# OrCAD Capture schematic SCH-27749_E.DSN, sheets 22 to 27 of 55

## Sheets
22 T4240 Grounds: size C
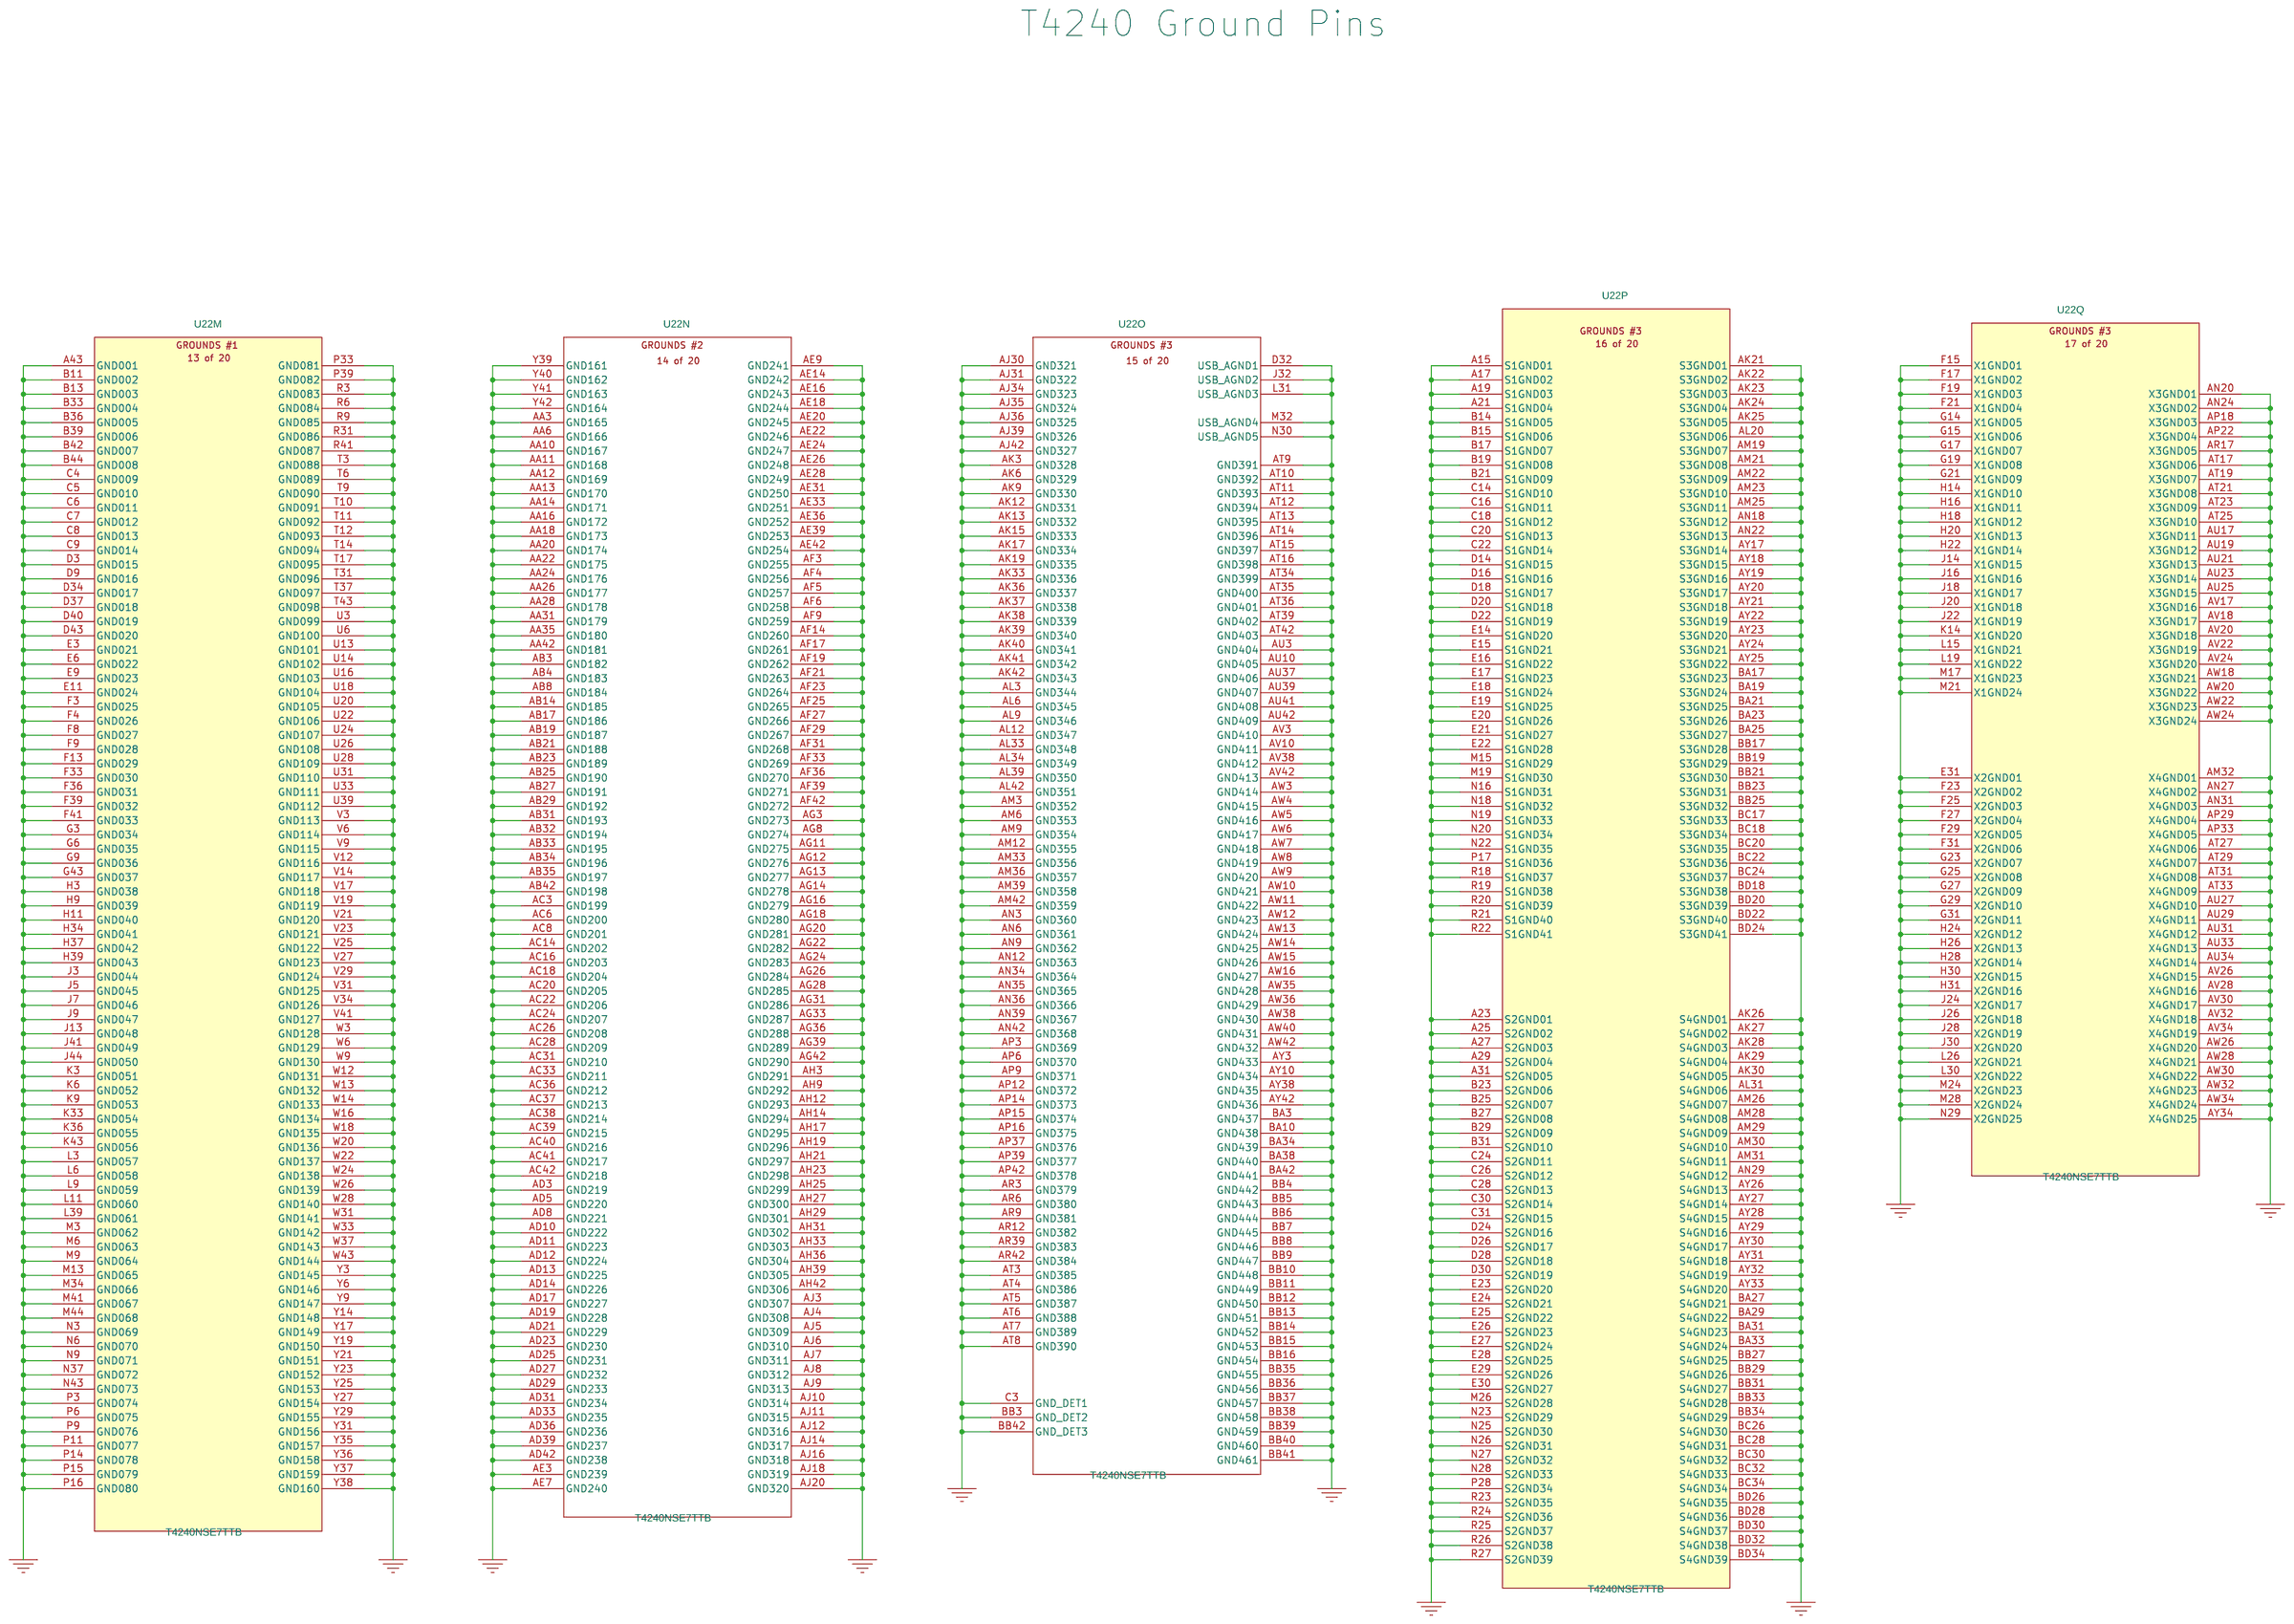
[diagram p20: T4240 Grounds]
23 T4240 NC: size C
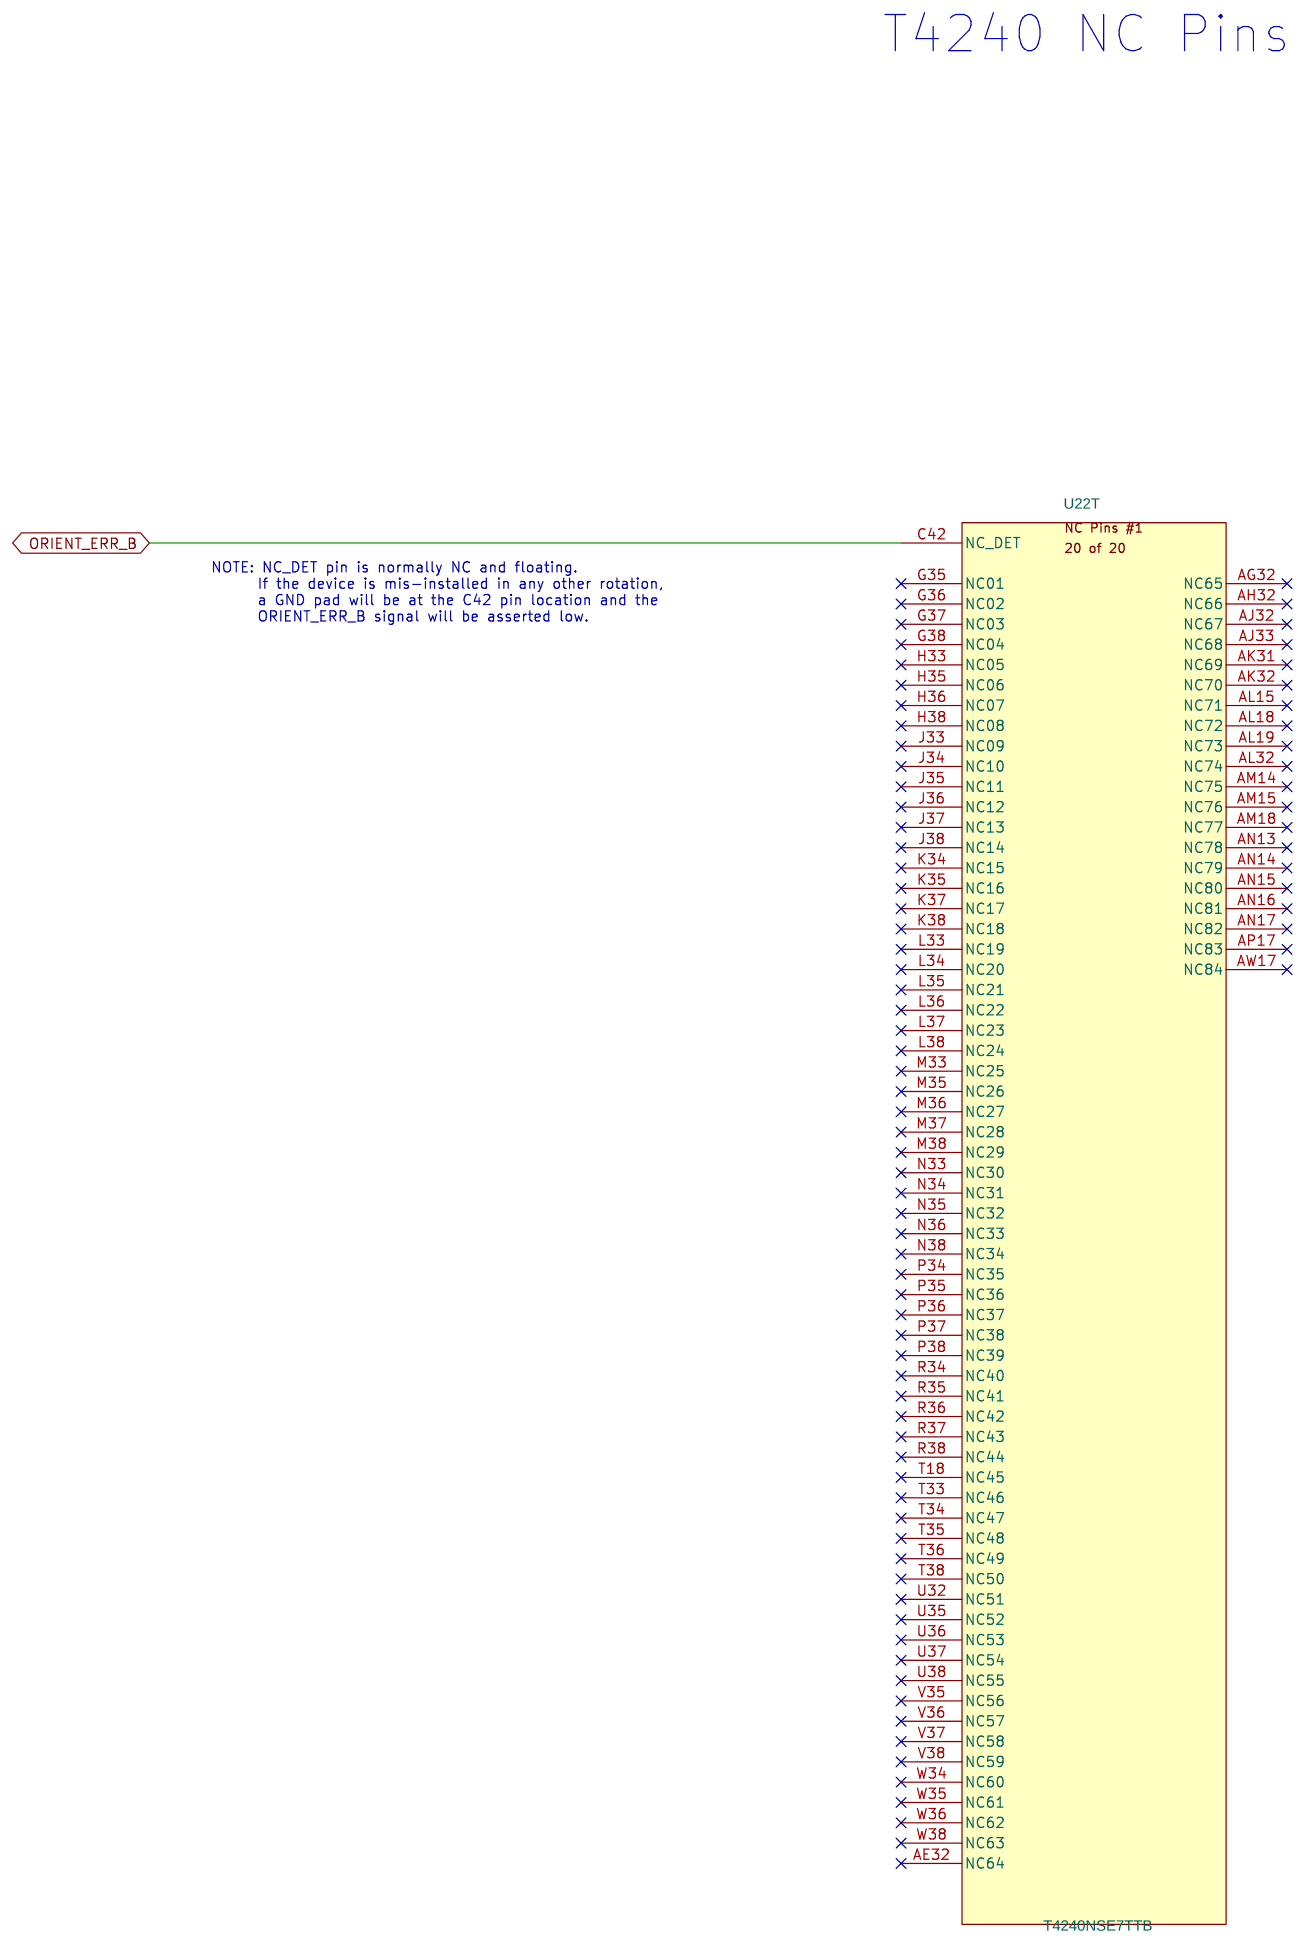
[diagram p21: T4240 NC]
24 Clock Generator: size C
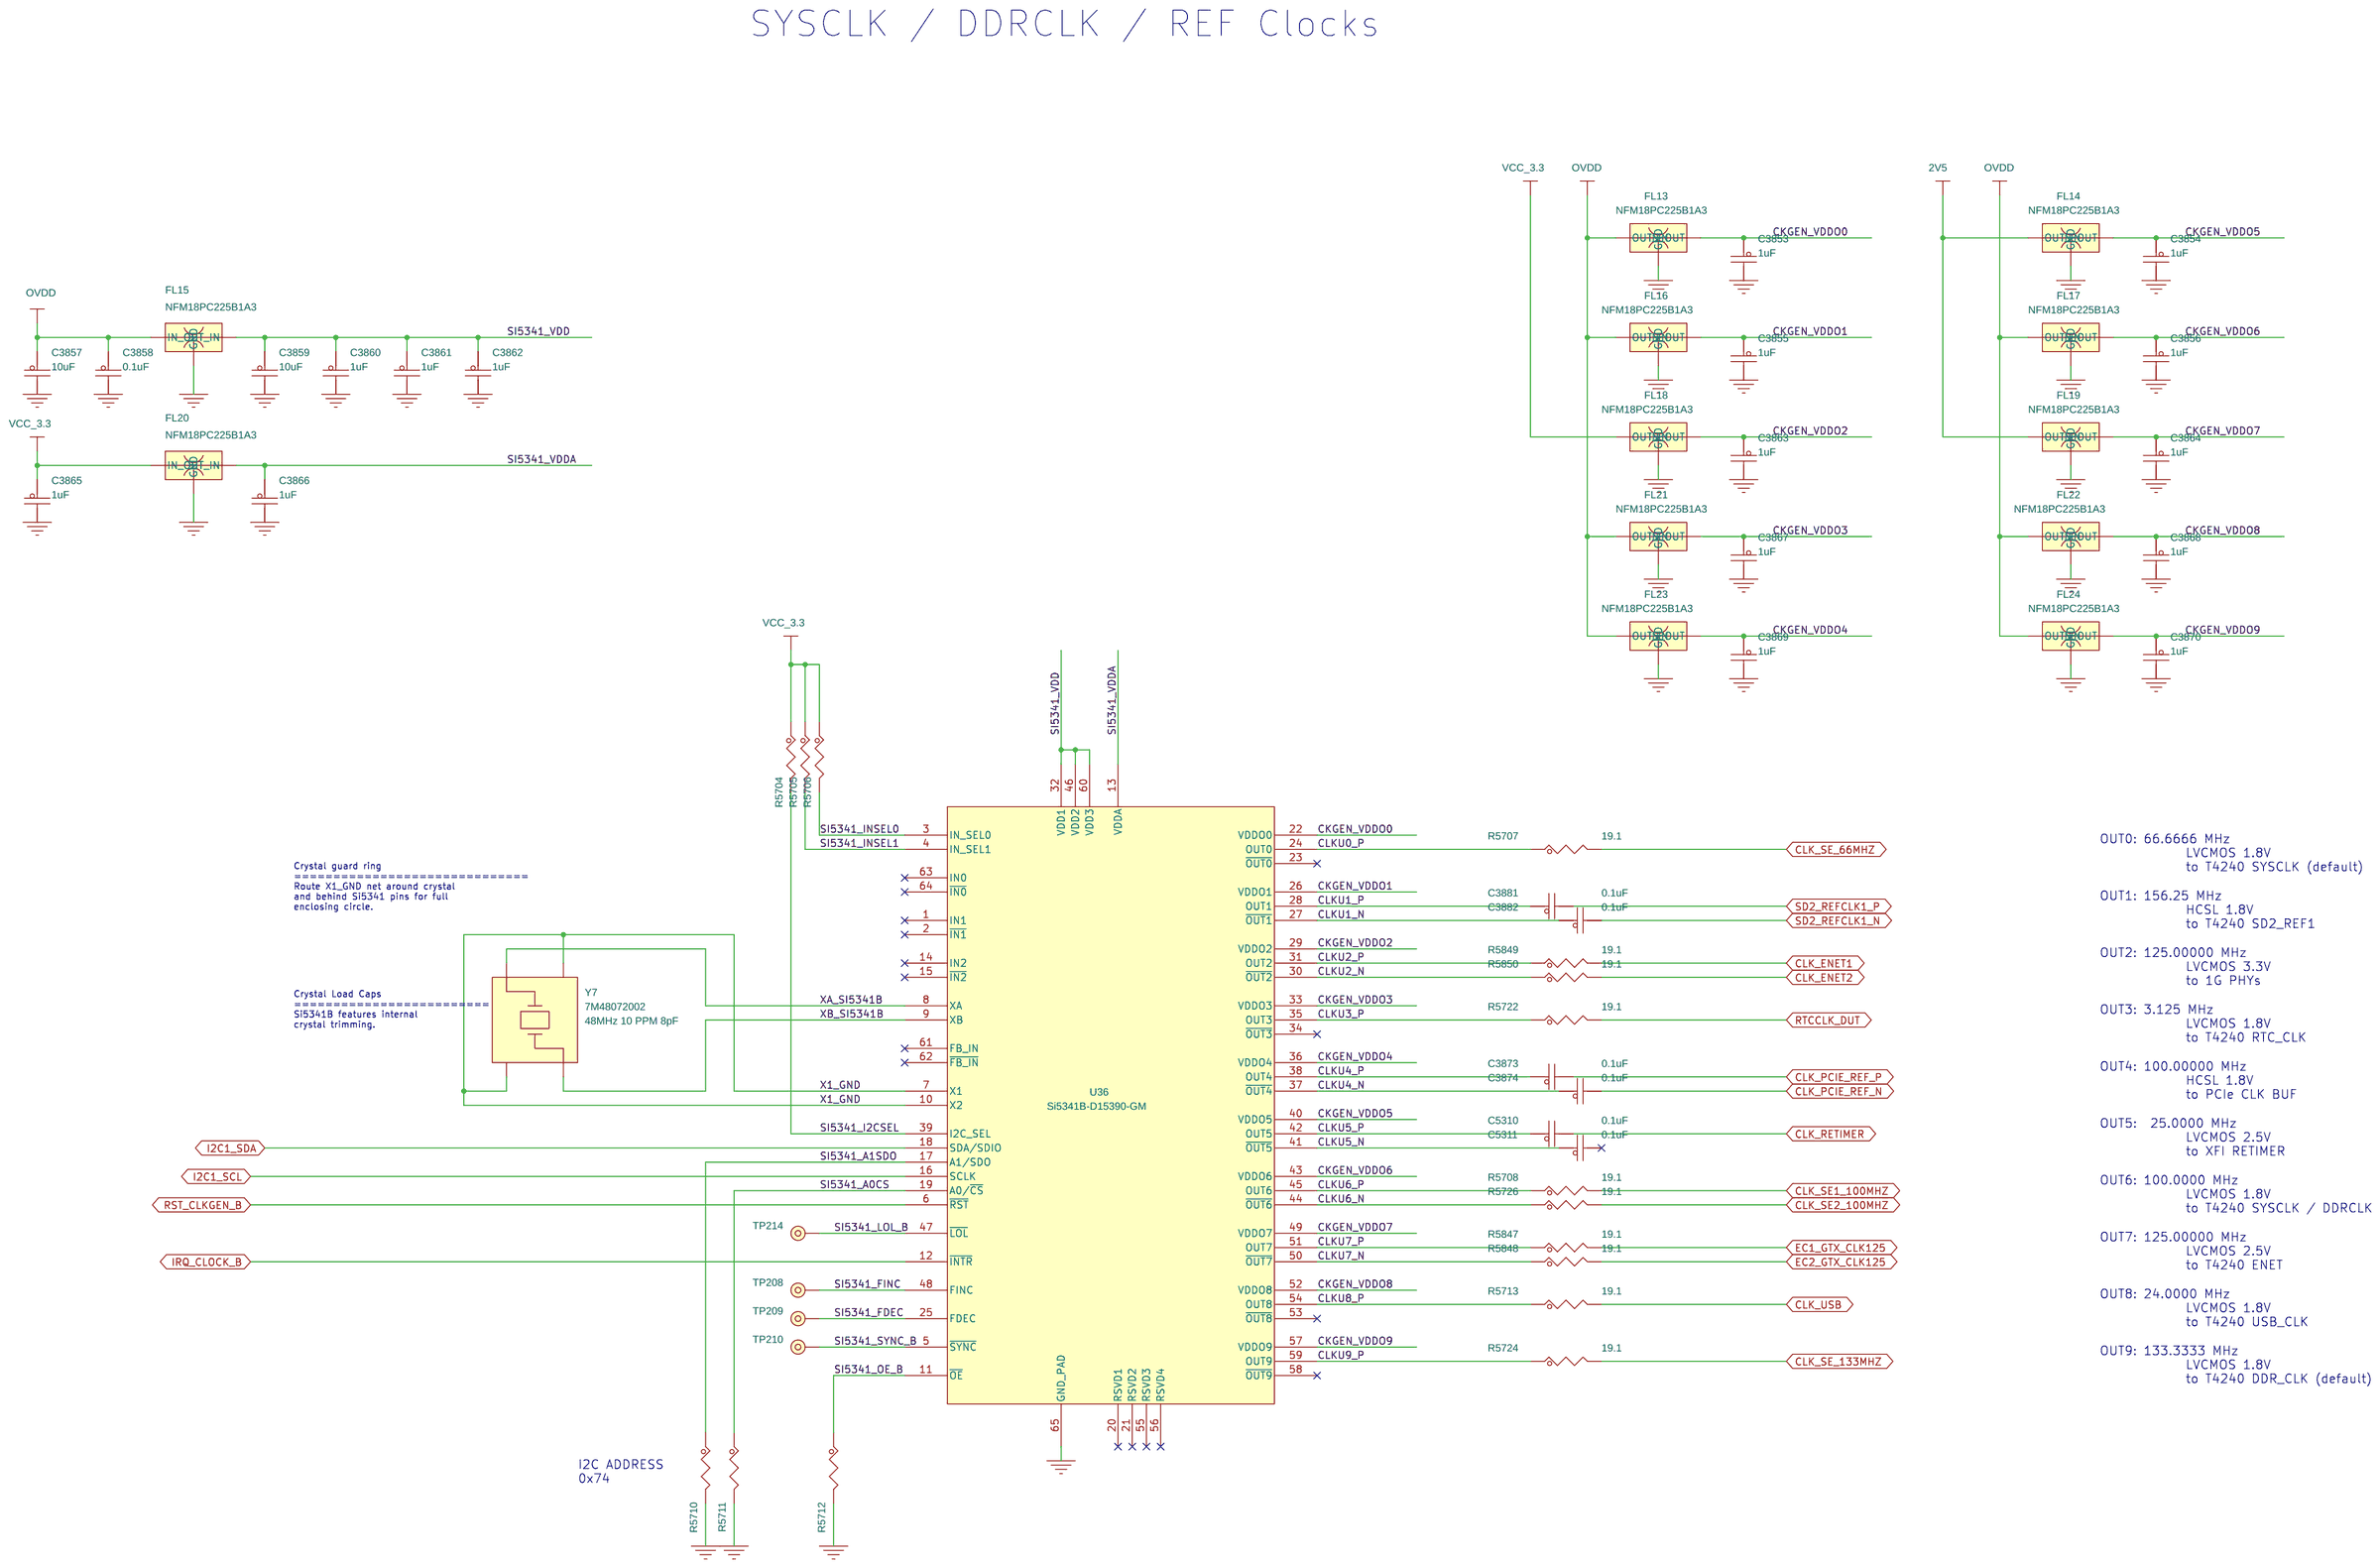
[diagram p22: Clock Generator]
25 PCIe & DUT Clock Buffers: size C
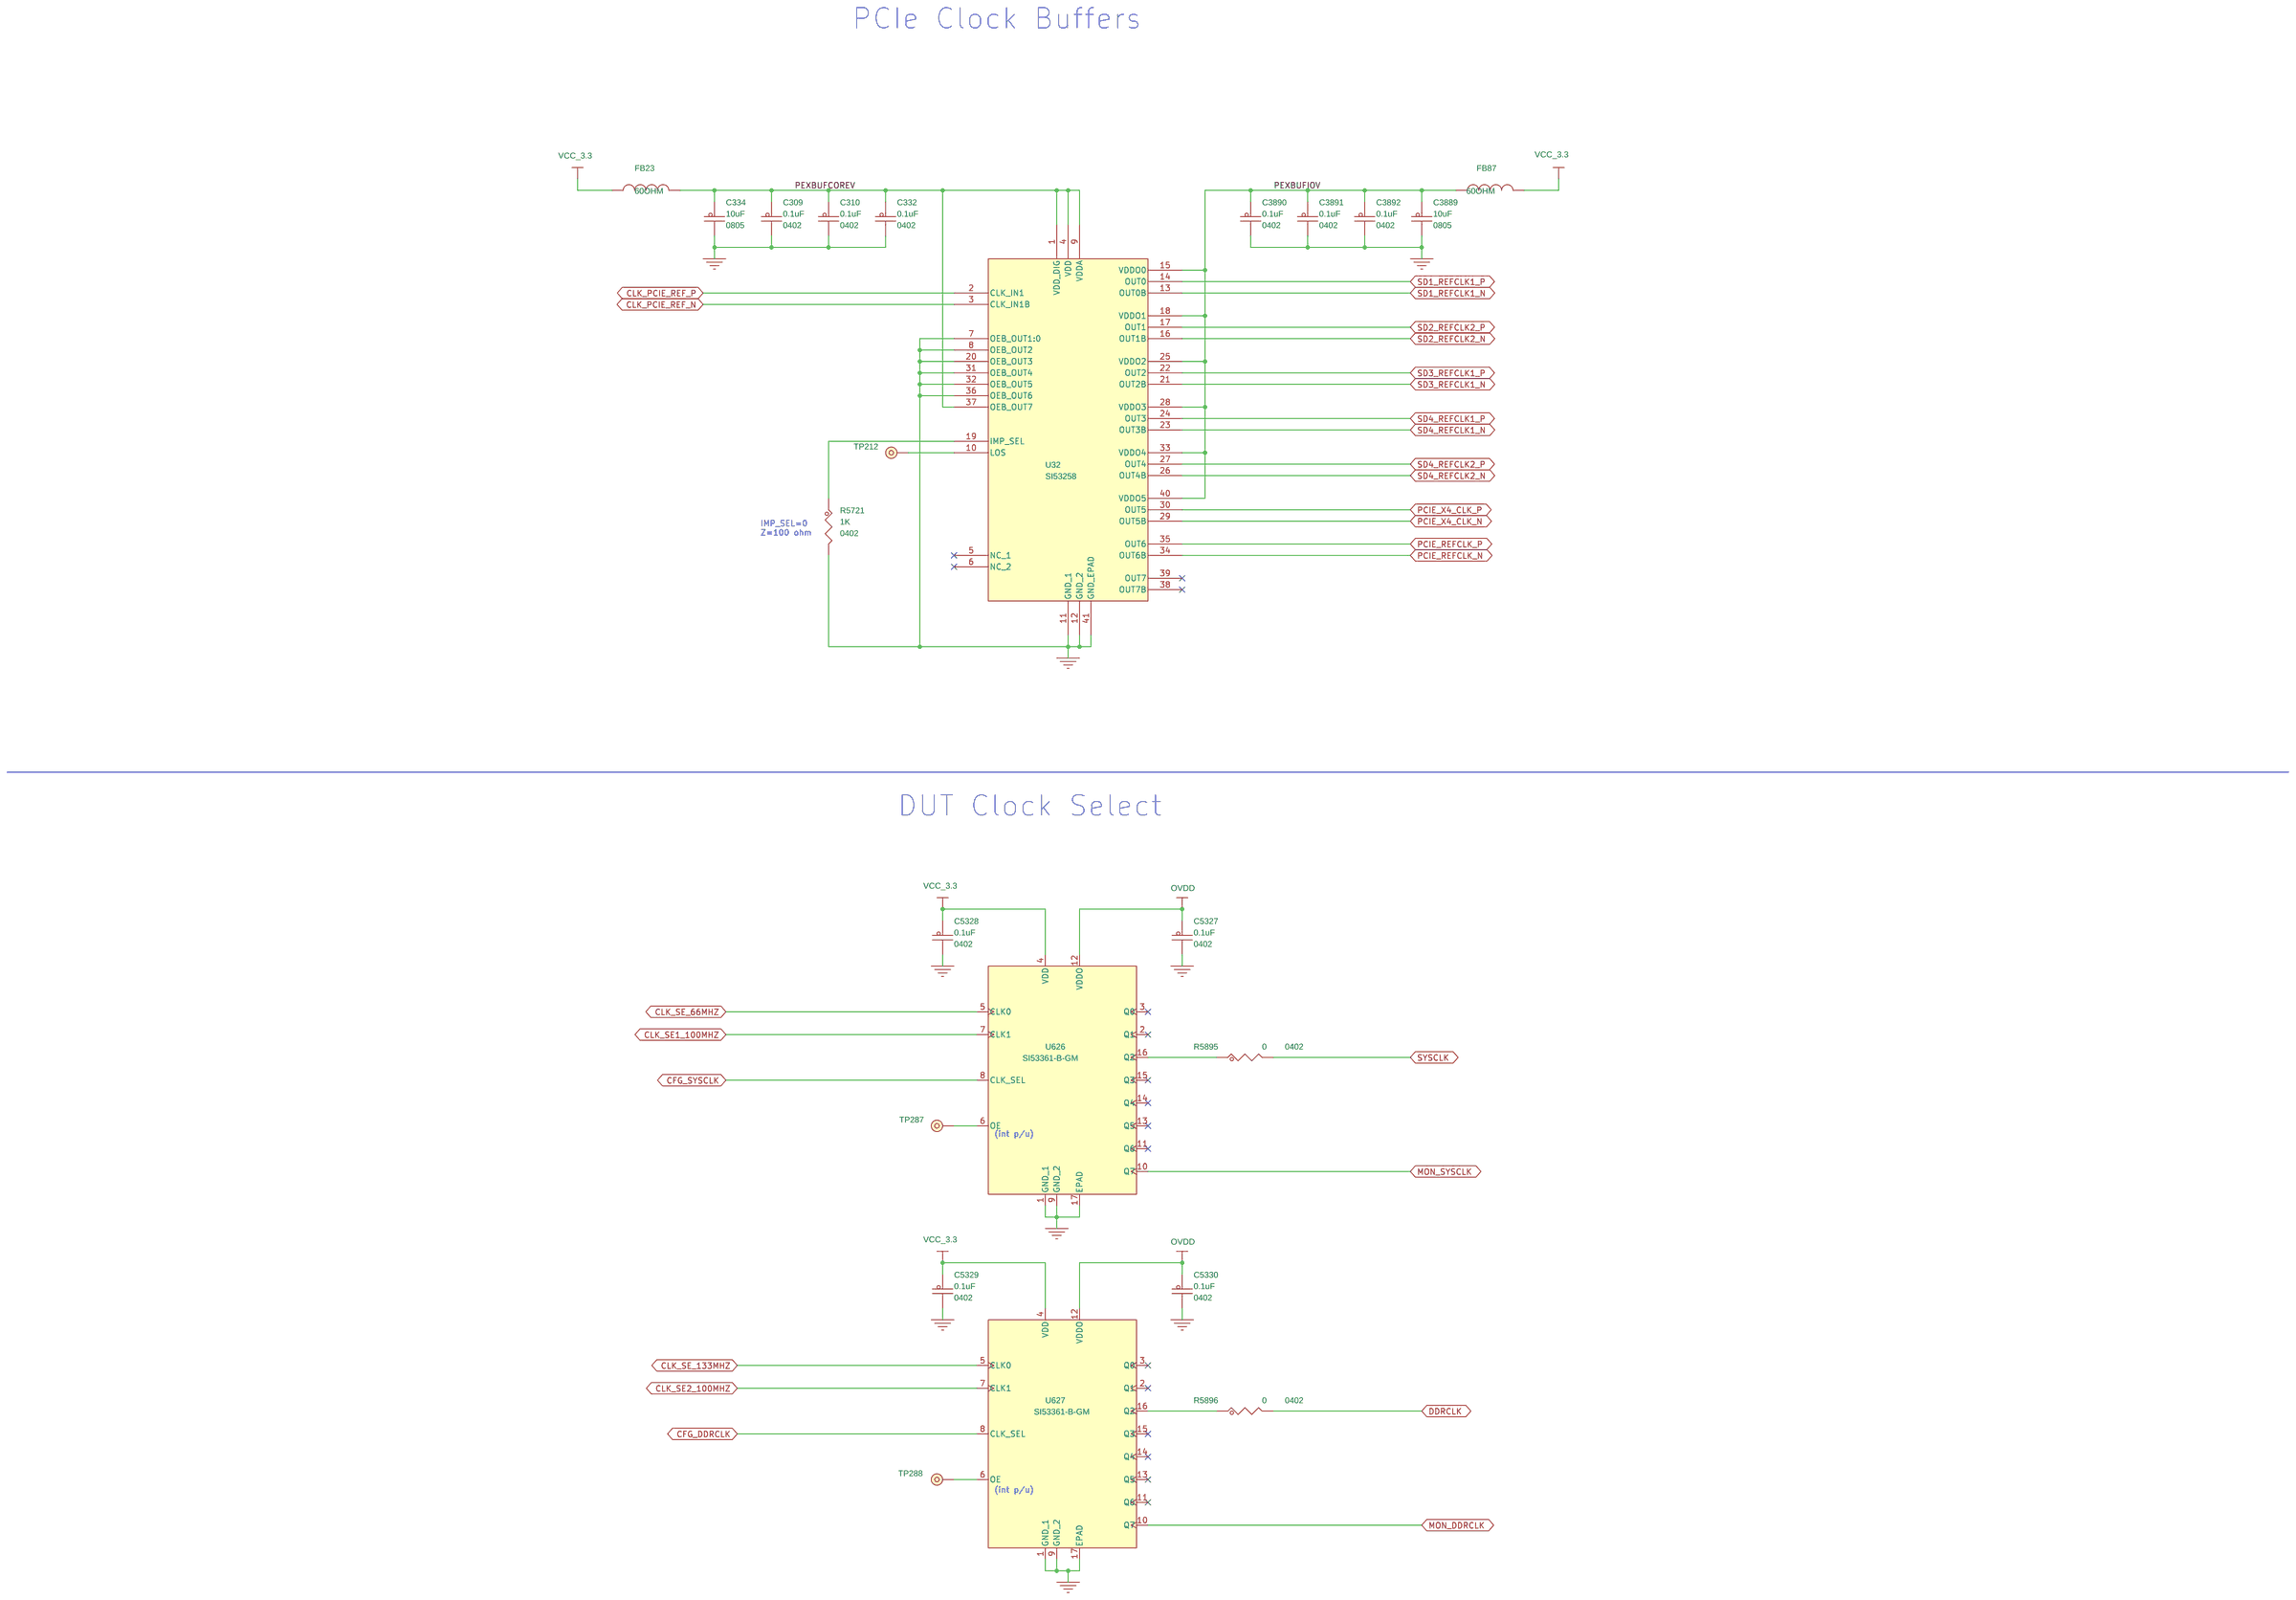
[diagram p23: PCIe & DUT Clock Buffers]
26 reserved (2)
27 T4240 System Block + COP: size C
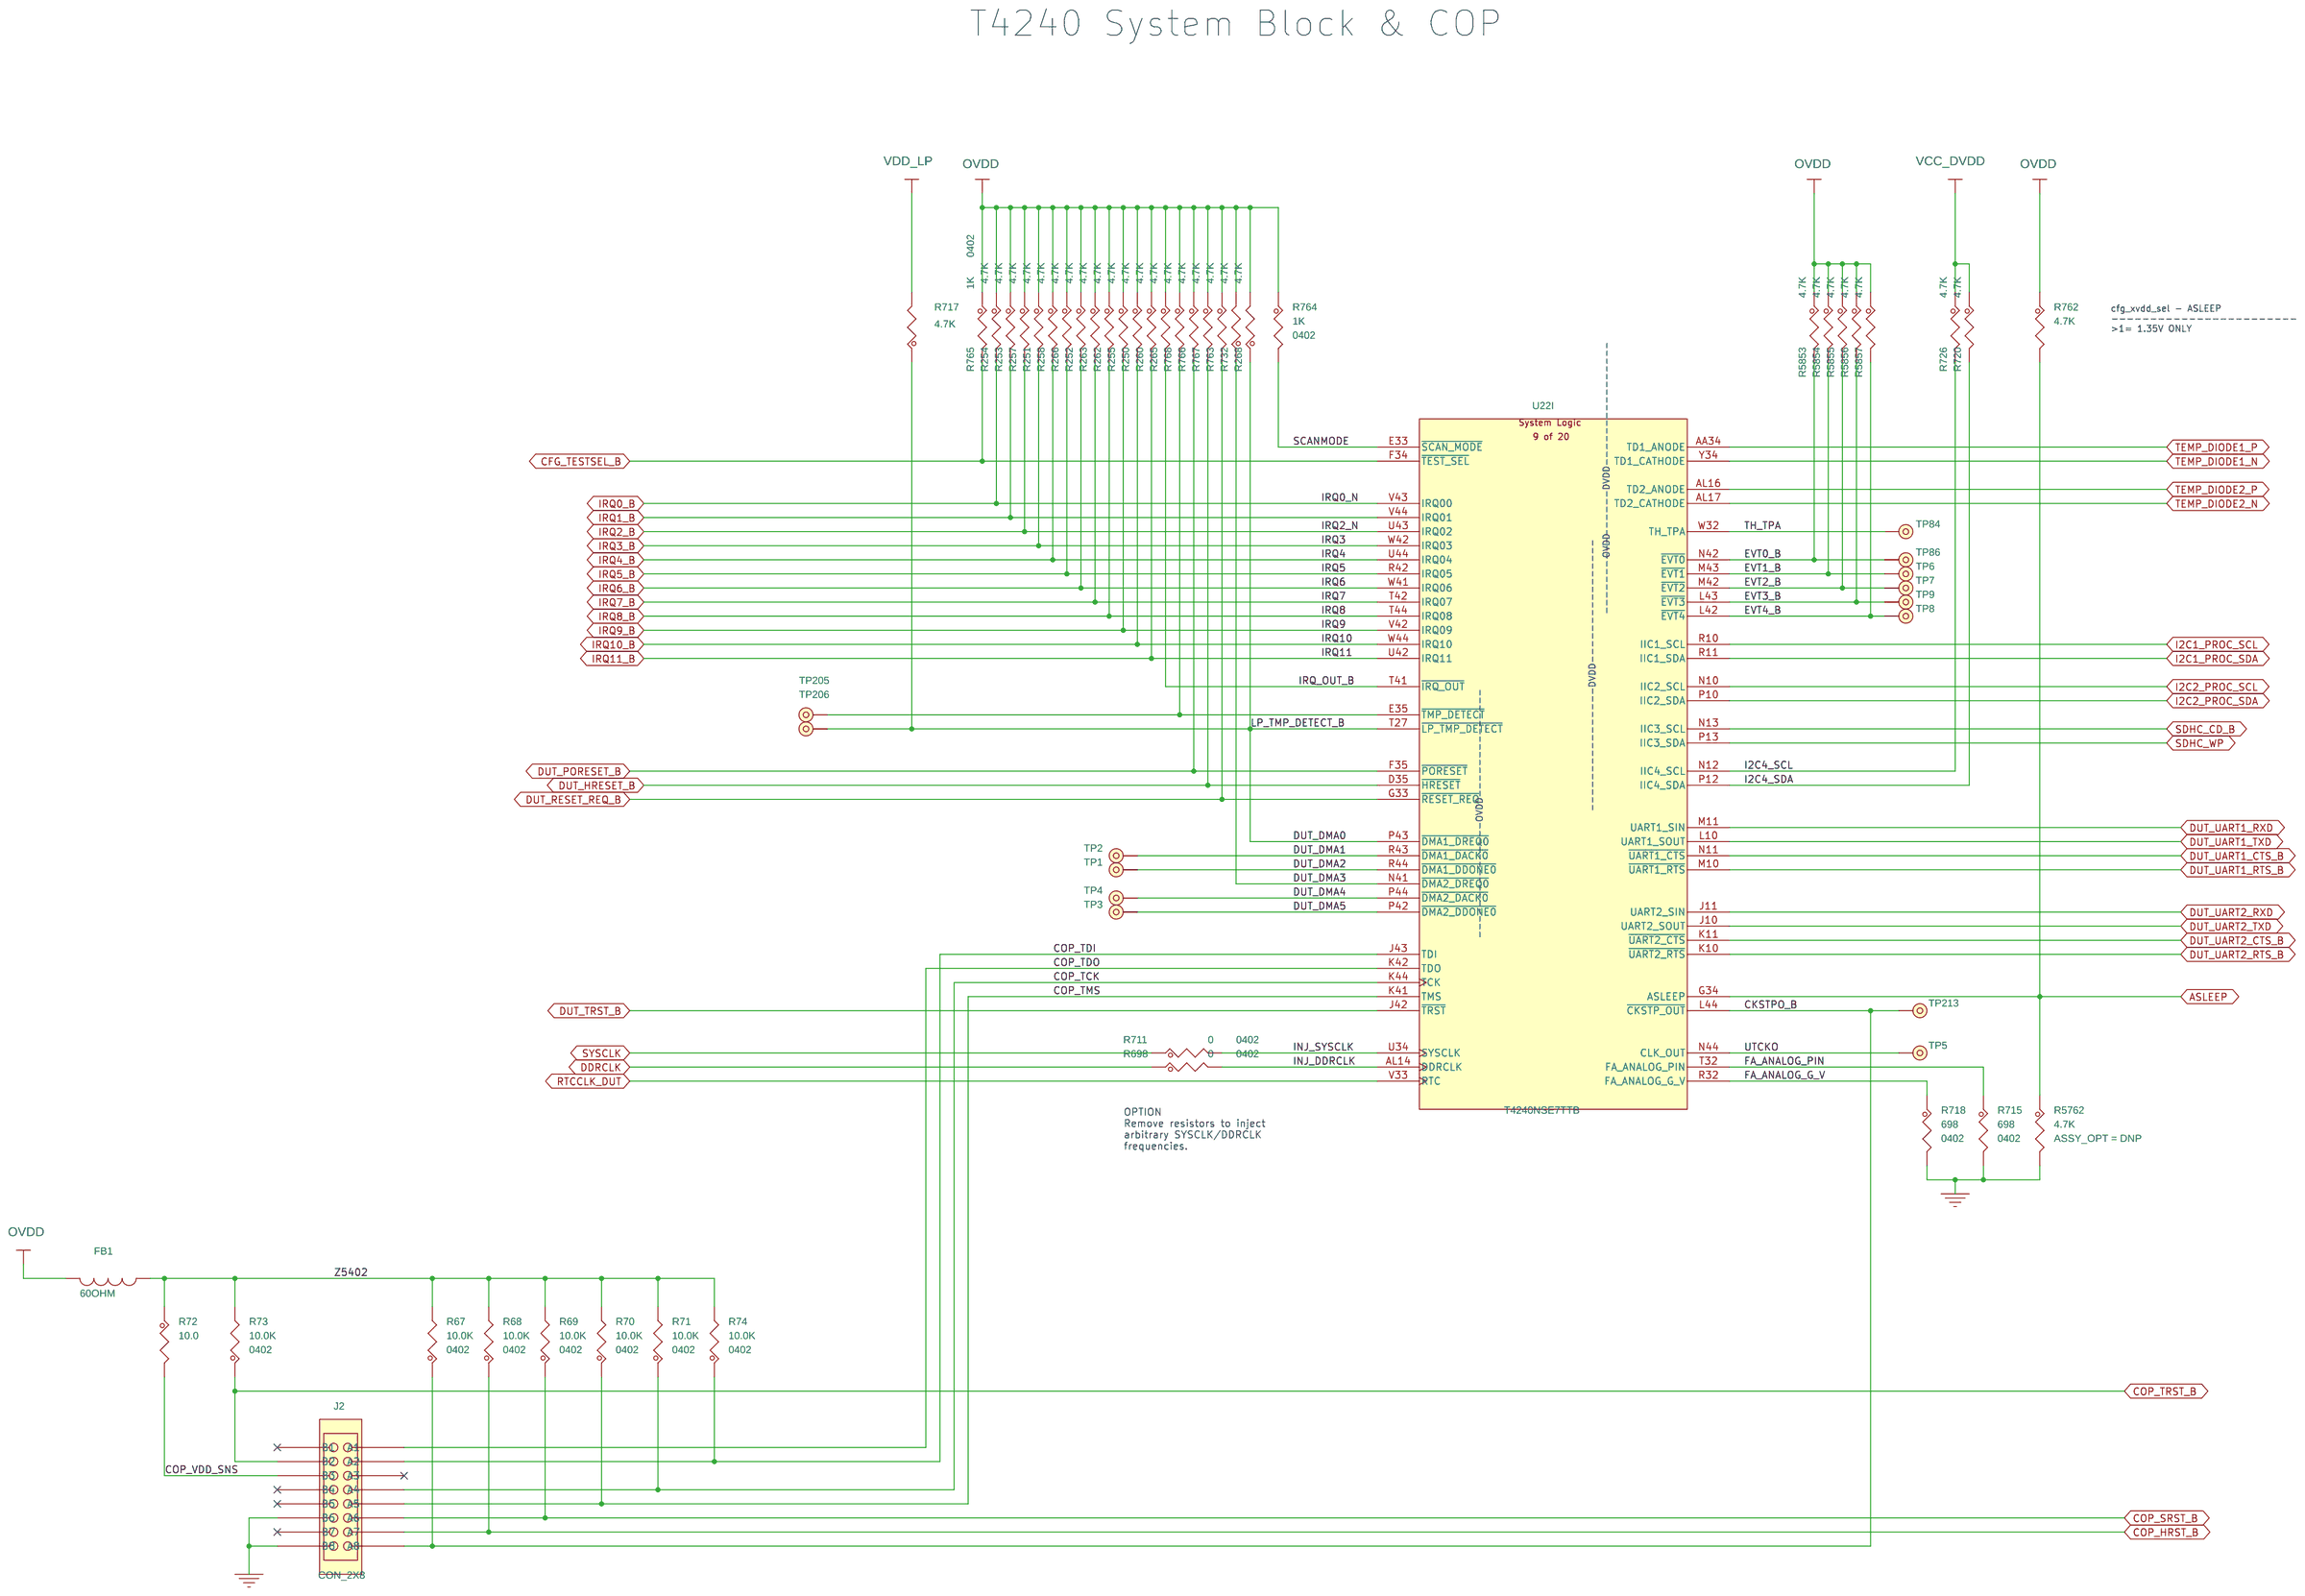
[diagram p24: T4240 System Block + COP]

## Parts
sheet Clock Generator
C3853  1uF  [CC0402_HD]
C3854  1uF  [CC0402_HD]
C3855  1uF  [CC0402_HD]
C3856  1uF  [CC0402_HD]
C3857  10uF  [CC0603_OV]
C3858  0.1uF  [CC0402_HD]
C3859  10uF  [CC0603_OV]
C3860  1uF  [CC0402_HD]
C3861  1uF  [CC0402_HD]
C3862  1uF  [CC0402_HD]
C3863  1uF  [CC0402_HD]
C3864  1uF  [CC0402_HD]
C3865  1uF  [CC0402_HD]
C3866  1uF  [CC0402_HD]
C3867  1uF  [CC0402_HD]
C3868  1uF  [CC0402_HD]
C3869  1uF  [CC0402_HD]
C3870  1uF  [CC0402_HD]
C3873  0.1uF  [CC0402_HD]
C3874  0.1uF  [CC0402_HD]
C3881  0.1uF  [CC0402_HD]
C3882  0.1uF  [CC0402_HD]
C5310  0.1uF  [CC0402_HD]
C5311  0.1uF  [CC0402_HD]
FL13  NFM18PC225B1A3  [cc0603_nfm18pc]
FL14  NFM18PC225B1A3  [cc0603_nfm18pc]
FL15  NFM18PC225B1A3  [cc0603_nfm18pc]
FL16  NFM18PC225B1A3  [cc0603_nfm18pc]
FL17  NFM18PC225B1A3  [cc0603_nfm18pc]
FL18  NFM18PC225B1A3  [cc0603_nfm18pc]
FL19  NFM18PC225B1A3  [cc0603_nfm18pc]
FL20  NFM18PC225B1A3  [cc0603_nfm18pc]
FL21  NFM18PC225B1A3  [cc0603_nfm18pc]
FL22  NFM18PC225B1A3  [cc0603_nfm18pc]
FL23  NFM18PC225B1A3  [cc0603_nfm18pc]
FL24  NFM18PC225B1A3  [cc0603_nfm18pc]
R5704  4.7K  [RC0402_25]
R5705  4.7K  [RC0402_25]
R5706  4.7K  [RC0402_25]
R5707  19.1  [RC0402_25]
R5708  19.1  [RC0402_25]
R5710  4.7K  [RC0402_25]
R5711  4.7K  [RC0402_25]
R5712  4.7K  [RC0402_25]
R5713  19.1  [RC0402_25]
R5722  19.1  [RC0402_25]
R5724  19.1  [RC0402_25]
R5726  19.1  [RC0402_25]
R5847  19.1  [RC0402_25]
R5848  19.1  [RC0402_25]
R5849  19.1  [RC0402_25]
R5850  19.1  [RC0402_25]
TP208  TPAD_020  [tpad_020_top]
TP209  TPAD_020  [tpad_020_top]
TP210  TPAD_020  [tpad_020_top]
TP214  TPAD_020  [tpad_020_top]
U36  Si5341B-D15390-GM  [qfn64_0p5_9x9c]
Y7  7M48072002  [xtal_4_3p3x2p6mm]
sheet PCIe & DUT Clock Buffers
C309  0.1uF  [CC0402_HD]
C310  0.1uF  [CC0402_HD]
C332  0.1uF  [CC0402_HD]
C334  10uF  [CC0603_OV]
C3889  10uF  [CC0603_OV]
C3890  0.1uF  [CC0402_HD]
C3891  0.1uF  [CC0402_HD]
C3892  0.1uF  [CC0402_HD]
C5327  0.1uF  [CC0402_HD]
C5328  0.1uF  [CC0402_HD]
C5329  0.1uF  [CC0402_HD]
C5330  0.1uF  [CC0402_HD]
FB23  60OHM  [ind_1p8x1mm_sm]
FB87  60OHM  [ind_1p8x1mm_sm]
R5721  1K  [RC0402_25]
R5895  0  [RC0402_25]
R5896  0  [RC0402_25]
TP212  TPAD_020  [tpad_020_top]
TP287  TPAD_020  [tpad_020_top]
TP288  TPAD_020  [tpad_020_top]
U32  SI53258  [qfn40_0p5_6x6_4p6ep]
U626  SI53361-B-GM  [qfn16_0p5_3x3mm]
U627  SI53361-B-GM  [qfn16_0p5_3x3mm]
sheet T4240 DDR Controller #2
U22  T4240NSE7TTB  [BGA1932_1MM_45X45MM]  (sections A,B,C,D,E,F,G,H,I,J,K,L,M,N,O,P,Q,R,S,T)
sheet T4240 System Block + COP
FB1  60OHM  [ind_1p8x1mm_sm]
J2  CON_2X8  [HDR208_4W]
R67  10.0K  [RC0402_25]
R68  10.0K  [RC0402_25]
R69  10.0K  [RC0402_25]
R70  10.0K  [RC0402_25]
R71  10.0K  [RC0402_25]
R72  10.0  [RC0402_25]
R73  10.0K  [RC0402_25]
R74  10.0K  [RC0402_25]
R250  4.7K  [RC0402_25]
R251  4.7K  [RC0402_25]
R252  4.7K  [RC0402_25]
R253  4.7K  [RC0402_25]
R254  4.7K  [RC0402_25]
R255  4.7K  [RC0402_25]
R257  4.7K  [RC0402_25]
R258  4.7K  [RC0402_25]
R260  4.7K  [RC0402_25]
R262  4.7K  [RC0402_25]
R263  4.7K  [RC0402_25]
R265  4.7K  [RC0402_25]
R266  4.7K  [RC0402_25]
R268  4.7K  [RC0402_25]
R698  0  [RC0402_25]
R711  0  [RC0402_25]
R715  698  [RC0402_25]
R717  4.7K  [RC0402_25]
R718  698  [RC0402_25]
R720  4.7K  [RC0402_25]
R726  4.7K  [RC0402_25]
R732  4.7K  [RC0402_25]
R762  4.7K  [RC0402_25]
R763  4.7K  [RC0402_25]
R764  1K  [RC0402_25]
R765  1K  [RC0402_25]
R766  4.7K  [RC0402_25]
R767  4.7K  [RC0402_25]
R768  4.7K  [RC0402_25]
R5762  4.7K  [RC0402_25]
R5853  4.7K  [RC0402_25]
R5854  4.7K  [RC0402_25]
R5855  4.7K  [RC0402_25]
R5856  4.7K  [RC0402_25]
R5857  4.7K  [RC0402_25]
TP1  TPAD_020  [tpad_020_top]
TP2  TPAD_020  [tpad_020_top]
TP3  TPAD_020  [tpad_020_top]
TP4  TPAD_020  [tpad_020_top]
TP5  TPAD_020  [tpad_020_top]
TP6  TPAD_020  [tpad_020_top]
TP7  TPAD_020  [tpad_020_top]
TP8  TPAD_020  [tpad_020_top]
TP9  TPAD_020  [tpad_020_top]
TP84  TPAD_020  [tpad_020_top]
TP86  TPAD_020  [tpad_020_top]
TP205  TPAD_020  [tpad_020_top]
TP206  TPAD_020  [tpad_020_top]
TP213  TPAD_020  [tpad_020_top]

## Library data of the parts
C3853-C3856 C3860-C3870 = CAP_NP: CAP CER 1uF 10V 10% X7S 0402; AGILE_PN: 150-80357; CAD_APPROVED: Yes; FPLIST: CC0402_25,CC0402_HD,0402_CC,capc0402_l; HEIGHT: 0.6MM; MFG_NAME01: MURATA; MFG_PN01: GRM155C71A105KE11D; Package Size: 0402; ROHS: Yes; Rated Voltage: 10V; SIGNAL_MODEL: DEFAULT_CAPACITOR_1e+06pF_2_1; Temp Range: -55C to +125C; Tolerance: 10%; VOLTAGE: 10V
C3857 C3859 = CAP_NP: CAP CER 10UF 10V 10% X5R 0603; AGILE_PN: 150-78675; CAD_APPROVED: Yes; FPLIST: CC0603_OV,CC0603,0603_CC; HEIGHT: 1.016MM; MFG_NAME01: MURATA; MFG_PN01: GRM188R61A106KE69D; PRIORITY_PN: 021-00358; ROHS: Yes; ROOM: SDHC; Rated Voltage: 10V; SIGNAL_MODEL: DEFAULT_CAPACITOR_1e+07pF_2_1; TOL: 10%; Temp Range: -55C to +85C; Temp_Range: -55°C ~ 85°C; Tolerance: 10%; VOLTAGE: 10v
C3858 = CAP_NP: CAP CER 0.1uF 16V 10% X7R AEC-Q200 0402; AGILE_PN: 150-79025; CAD_APPROVED: Yes; FPLIST: CC0402_25,CC0402_HD,0402_CC,capc0402_l; HEIGHT: 0.55MM; MFG_NAME01: MURATA; MFG_PN01: GCM155R71C104KA55D; PRIORITY_PN: 021-00389; Package Size: 0402; Package Type: ø180mm Reel PAPER; ROHS: Yes; ROOM: RS232; Rated Voltage: 16V; SIGNAL_MODEL: DEFAULT_CAPACITOR_100000pF_2_1; TOL: 10%; Temp Range: -55C to +125C; Tolerance: 10%; VOLTAGE: 35V
C3873 C3874 C3881 C3882 C5310 C5311 = CAP_NP: CAP CER 0.1uF 16V 10% X7R AEC-Q200 0402; AGILE_PN: 150-79025; CAD_APPROVED: Yes; FPLIST: CC0402_25,CC0402_HD,0402_CC,capc0402_l; HEIGHT: 0.55MM; MFG_NAME01: MURATA; MFG_PN01: GCM155R71C104KA55D; PRIORITY_PN: 021-00389; Package Size: 0402; Package Type: ø180mm Reel PAPER; ROHS: Yes; ROOM: MII_MUX; Rated Voltage: 16V; Temp Range: -55C to +125C; Tolerance: 10%; VOLTAGE: 35V
FL13-FL24 = NFM18PC225B1A3: CAP FILTER EMI 2.2uF 10V 20% -- 0603; 3D_Mechanical_Footprint_File: http://fcl.am.freescale.net/ALLEGRO/step/cc0603_nfm18pc.STEP; AGILE_PN: 150-79428; CAD_APPROVED: Yes; HEIGHT: 0.9MM; MFG_NAME01: MURATA; MFG_PN01: NFM18PC225B1A3D; ROHS: Yes; Rated Voltage: 10V; Temp Range: -40C to +85C; Temp_Range: -40 C to +85 C; Tolerance: 20%; VOLTAGE: 10V
R5704-R5706 R5710-R5712 = RES: RES MF 4.7K 1/10W 5% AEC-Q200 0402; AGILE_PN: 470-82064; CAD_APPROVED: Yes; FPLIST: RC0402_25,RC0402_HD,0402_CC,RC0402_X2; HEIGHT: 0.41mm; MFG_NAME01: KOA SPEER; MFG_PN01: RK73B1ETTP472J; PRIORITY_PN: 006-00619; ROHS: Yes; ROOM: DUT_CLOSE; SIGNAL_MODEL: DEFAULT_RESISTOR_4700OHM_2_1; TOL: 1%; Temp Range: -55C to +155C; Tolerance: 5%; VOLTAGE: 1/16W
R5707 R5708 R5713 R5722 R5724 R5726 R5847-R5850 = RES: RES MF 19.1 OHM 1/10W 1% AEC-Q200 0402; AGILE_PN: 470-30669; CAD_APPROVED: Yes; FPLIST: RC0402_25,RC0402_HD,0402_CC; HEIGHT: 0.40 MM; MFG_NAME01: KOA SPEER; MFG_PN01: RK73H1ETTP19R1F; ROHS: Yes; Temp Range: -55°C to +155°C; Temp_Range: -55°C to +155°C; Tolerance: 1%; VOLTAGE: 50V
TP1-TP9 TP84 TP86 TP205 TP206 TP208-TP210 TP212-TP214 TP287 TP288 = T_POINT_TH: TEST POINT PAD 20 MILS SMT, NOT PART TO ORDER; AGILE_PN: 211-81036; CAD_APPROVED: Yes; FPLIST: tpad_020_top,tpad_020_btm_nsp; HEIGHT: 0.127MM; MFG_NAME01: NO PART ORDER; MFG_PN01: NA; ROHS: Yes
U36 = Si5341B_64P_EP: IC CLK MUX 4:10 DIFF LVPECL/LVDS 350MHz 1.8V/3.3V QFN64; 3D_Mechanical_Footprint_File: http://fcl.am.freescale.net/ALLEGRO/step/qfn64_0p5_9x9c.step; AGILE_PN: 312-83853; CAD_APPROVED: Yes; HEIGHT: 0.90 MM; MFG_NAME01: SKYWORKS SOLUTIONS, INC.; ROHS: Yes; Temp Range: -40C to +85C; VOLTAGE: 1.8V/3.3V
Y7 = XTAL_13Y: XTAL 48MHz 10PPM 8pF SMD; AGILE_PN: 230-78080; CAD_APPROVED: Yes; HEIGHT: 0.8MM; MFG_NAME01: TXC CORP; NOTE: 48MHz 10 PPM 8pF; ROHS: Yes
C309 C310 C332 C3890-C3892 C5327-C5330 = CAP_NP: CAP CER 0.1uF 16V 10% X7R AEC-Q200 0402; AGILE_PN: 150-79025; CAD_APPROVED: Yes; FPLIST: CC0402_25,CC0402_HD,0402_CC,capc0402_l; HEIGHT: 0.55MM; MFG_NAME01: MURATA; MFG_PN01: GCM155R71C104KA55D; Package: 0402; Package Size: 0402; Package Type: ø180mm Reel PAPER; Part Number: 4CC104B163X00; Product Name: (H)MLCC 0.1uF/16V +-10% 0402 X7R; ROHS: Yes; Rated Voltage: 16V; Temp Range: -55C to +125C; Tolerance: 10%
C334 C3889 = CAP_NP: CAP CER 10UF 10V 10% X5R 0603; AGILE_PN: 150-78675; CAD_APPROVED: Yes; FPLIST: CC0603_OV,CC0603,0603_CC_NSP; HEIGHT: 1.016MM; MFG_NAME01: MURATA; MFG_PN01: GRM188R61A106KE69D; Package: 0805; Part Number: 4CC106D101X00; Product Name: (H)MLCC 10uF/10V +/-10% 0805 X5R; ROHS: Yes; Rated Voltage: 10V; Temp Range: -55C to +85C; Tolerance: 10%
FB1 FB23 FB87 = INDUCTOR: IND FER BEAD 60OHM@100MHz 3A 25% 0603; 3D_Mechanical_Footprint_File: http://fcl.am.freescale.net/ALLEGRO/step/ind_1p8x1mm_sm.step; AGILE_PN: 180-78461; CAD_APPROVED: Yes; HEIGHT: 1MM; MFG_NAME01: WURTH ELEKTRONIK EISOS GMBH & CO. KG (ELECTRONIC & ELECTROMEHANICAL COMP); MFG_PN01: 742792602; ROHS: Yes
R764 R765 R5721 = RES: RES 1K 1/16W 5% 0402; AGILE_PN: 470-80721; CAD_APPROVED: Yes; FPLIST: RC0402_25,RC0402_HD,0402_CC; HEIGHT: 0.4 MM; MFG_NAME01: TE CONNECTIVITY LTD; MFG_PN01: CRG0402J1K0; Package: 0402; Part Number: 4RC1002B11X00; Product Name: (H)RES 1K 1/16W 0402 1% PBFREE; ROHS: Yes; Tolerance: 5%
R698 R711 R5895 R5896 = RES: RES MF ZERO OHM 1/10W -- 0402; AGILE_PN: 470-79965; CAD_APPROVED: Yes; FPLIST: RC0402_25,RC0402_HD,RC0402_X2,0402_CC,RC0402_X3; HEIGHT: 0.4MM; MFG_NAME01: PANASONIC; MFG_PN01: ERJ-2GE0R00X; Package: 0402; Part Number: 4RC0000B51X00; Product Name: (H)RES 0E 1/16W 0402 5% PBFREE; ROHS: Yes; Temp Range: –55 °C to +155 °C
U32 = Si53258: IC CLK BUFF 8 CLK-OUT PCIE 100MHz 1.8-3.3V QFN40; AGILE_PN: 312-82930; CAD_APPROVED: Yes; HEIGHT: 0.9MM; MFG_NAME01: SILICON LABORATORIES; MFG_PN01: SI53258A-D01AM; ROHS: Yes; Temp Range: -40C to +105C; VOLTAGE: 1.8-3.3V
U626 U627 = SI53361: IC CLK BUF LOW JITTER 2:1 INPUT MUX 200MHz 1.71-3.63V QFN16; 3D_Mechanical_Footprint_File: http://fcl.am.freescale.net/ALLEGRO/step/qfn16_0p5_3x3mm.STEP; AGILE_PN: 312-83879; CAD_APPROVED: yes; HEIGHT: 0.9 MM; MFG_NAME01: Skyworks Solutions Inc.; Package Size: 16-QFN Exposed Pad; ROHS: Yes; Supply Voltage: 1.71V ~ 3.63V; Temp Range: -40  °C  +85 °C
U22 = T4240: IC MPU 64BIT T4240 1.8GHz 1.025V CRYPTO QorIQ PBGA1932; 3D_Mechanical_Footprint_File: http://fcl.am.freescale.net/ALLEGRO/step/bga1932_1mm_45x45mm.STEP; AGILE_PN: 330-77243; CAD_APPROVED: Yes; HEIGHT: 3.33 MM; MFG_NAME01: NXP SEMICONDUCTOR; Package Size: SOT1645-1; Part Number: 71F101G206X01; Product Name: (N)SOC FREESCALE:T4240NSE7TTB; ROHS: Yes; Temp Range: 0 to 105 °C
J2 = CONN_SHRHDR_8X2: CON 2X8 PLUG SHRD TH 100MIL CTR 365H AU 130L; 3D_Mechanical_Footprint_File: http://fcl.am.freescale.net/ALLEGRO/step/hdr208_4w.STEP; AGILE_PN: 210-75459; CAD_APPROVED: Yes; HEIGHT: 9.27 MM; MFG_NAME01: SAMTEC; MFG_PN01: TST-108-01-S-D; Package Size: TH-16; Package Type: TH; ROHS: Yes
R67-R71 R73 R74 = RES: RES MF 10.0K 1/16W 1% AEC-Q200 0402; AGILE_PN: 470-75416; CAD_APPROVED: Yes; FPLIST: RC0402_25,RC0402_HD,0402_CC; HEIGHT: 0.4MM; MFG_NAME01: KOA SPEER; MFG_PN01: RK73H1ETTP1002F; Package: 0402; Part Number: 4RC1003B11X00; Product Name: (H)RES 10K 1/16W 0402 1% PBFREE; ROHS: Yes; Temp Range: –55 °C to +155 °C; Tolerance: 1%
R72 = RES: RES MF 10.0 OHM 1/16W 1% 0402; 3D_Mechanical_Footprint_File: http://fcl.am.freescale.net/ALLEGRO/step/rc0402_25.STEP; AGILE_PN: 470-76090; CAD_APPROVED: Yes; FPLIST: RC0402_25,RC0402_HD,0402_CC,rc0402_ghwe; HEIGHT: 0.4MM; MFG_NAME01: BOURNS; MFG_PN01: CR0402-FX-10R0GLF; Part Number: 4RC1000C11X00; Product Name: (H)RES 10E 1/10W 0603 1% PBFREE; ROHS: Yes; Tolerance: 1%
R250-R255 R257 R258 R260 R262 R263 R265 R266 R268 R717 R720 R726 R732 R762 R763 R766-R768 R5853-R5857 = RES: RES MF 4.7K 1/10W 5% AEC-Q200 0402; AGILE_PN: 470-82064; CAD_APPROVED: Yes; FPLIST: RC0402_25,RC0402_HD,0402_CC,RC0402_X2; HEIGHT: 0.41mm; MFG_NAME01: KOA SPEER; MFG_PN01: RK73B1ETTP472J; ROHS: Yes; Temp Range: -55C to +155C; Tolerance: 5%
R715 R718 = RES: RES MF 698 OHM 1/16W 1% ACE-Q200 0402; AGILE_PN: 470-78342; CAD_APPROVED: Yes; FPLIST: RC0402_25,RC0402_HD,0402_CC; HEIGHT: 0.4MM; MFG_NAME01: KOA SPEER; MFG_PN01: RK73H1ETTP6980F; Package: 0402; Part Number: 4RC6981B11X00; Product Name: (H)RES 698E 1/16W 0402 1% PBFREE; ROHS: Yes; Tolerance: 1%
R5762 = RES: RES MF 4.7K 1/10W 5% AEC-Q200 0402; AGILE_PN: 470-82064; ASSY_OPT: DNP; CAD_APPROVED: Yes; FPLIST: RC0402_25,RC0402_HD,0402_CC,RC0402_X2; HEIGHT: 0.41mm; MFG_NAME01: KOA SPEER; MFG_PN01: RK73B1ETTP472J; ROHS: Yes; Temp Range: -55C to +155C; Tolerance: 5%

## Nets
2V5: FL14.3(OUT_IN) FL19.3(OUT_IN) ; also on sheet 15 20 38 45
GND: C309.2 C310.2 C332.2 C334.2 C3853.2 C3854.2 C3855.2 C3856.2 C3857.2 C3858.2 C3859.2 C3860.2 C3861.2 C3862.2 C3863.2 C3864.2 C3865.2 C3866.2 C3867.2 C3868.2 C3869.2 C3870.2 C3889.2 C3890.2 C3891.2 C3892.2 C5327.2 C5328.2 C5329.2 C5330.2 FL13.2(GND) FL14.2(GND) FL15.2(GND) FL16.2(GND) FL17.2(GND) FL18.2(GND) FL19.2(GND) FL20.2(GND) FL21.2(GND) FL22.2(GND) FL23.2(GND) FL24.2(GND) J2.12(B6) J2.16(B8) R715.2 R718.2 R5710.2 R5711.2 R5712.2 R5721.2 R5762.2 U22.A15(S1GND01) U22.A17(S1GND02) U22.A19(S1GND03) U22.A21(S1GND04) U22.A23(S2GND01) U22.A25(S2GND02) U22.A27(S2GND03) U22.A29(S2GND04) U22.A31(S2GND05) U22.A43(GND001) U22.AA3(GND165) U22.AA6(GND166) U22.AA10(GND167) U22.AA11(GND168) U22.AA12(GND169) U22.AA13(GND170) U22.AA14(GND171) U22.AA16(GND172) U22.AA18(GND173) U22.AA20(GND174) U22.AA22(GND175) U22.AA24(GND176) U22.AA26(GND177) U22.AA28(GND178) U22.AA31(GND179) U22.AA35(GND180) U22.AA42(GND181) U22.AB3(GND182) U22.AB4(GND183) U22.AB8(GND184) U22.AB14(GND185) U22.AB17(GND186) U22.AB19(GND187) U22.AB21(GND188) U22.AB23(GND189) U22.AB25(GND190) U22.AB27(GND191) U22.AB29(GND192) U22.AB31(GND193) U22.AB32(GND194) U22.AB33(GND195) U22.AB34(GND196) U22.AB35(GND197) U22.AB42(GND198) U22.AC3(GND199) U22.AC6(GND200) U22.AC8(GND201) U22.AC14(GND202) U22.AC16(GND203) U22.AC18(GND204) U22.AC20(GND205) U22.AC22(GND206) U22.AC24(GND207) U22.AC26(GND208) U22.AC28(GND209) U22.AC31(GND210) U22.AC33(GND211) U22.AC36(GND212) U22.AC37(GND213) U22.AC38(GND214) U22.AC39(GND215) U22.AC40(GND216) U22.AC41(GND217) U22.AC42(GND218) U22.AD3(GND219) U22.AD5(GND220) U22.AD8(GND221) U22.AD10(GND222) U22.AD11(GND223) U22.AD12(GND224) U22.AD13(GND225) U22.AD14(GND226) U22.AD17(GND227) U22.AD19(GND228) U22.AD21(GND229) U22.AD23(GND230) U22.AD25(GND231) U22.AD27(GND232) U22.AD29(GND233) U22.AD31(GND234) U22.AD33(GND235) U22.AD36(GND236) U22.AD39(GND237) U22.AD42(GND238) U22.AE3(GND239) U22.AE7(GND240) U22.AE9(GND241) U22.AE14(GND242) U22.AE16(GND243) U22.AE18(GND244) U22.AE20(GND245) U22.AE22(GND246) U22.AE24(GND247) U22.AE26(GND248) U22.AE28(GND249) U22.AE31(GND250) U22.AE33(GND251) U22.AE36(GND252) U22.AE39(GND253) U22.AE42(GND254) U22.AF3(GND255) U22.AF4(GND256) U22.AF5(GND257) U22.AF6(GND258) U22.AF9(GND259) U22.AF14(GND260) U22.AF17(GND261) U22.AF19(GND262) U22.AF21(GND263) U22.AF23(GND264) U22.AF25(GND265) U22.AF27(GND266) U22.AF29(GND267) U22.AF31(GND268) U22.AF33(GND269) U22.AF36(GND270) U22.AF39(GND271) U22.AF42(GND272) U22.AG3(GND273) U22.AG8(GND274) U22.AG11(GND275) U22.AG12(GND276) U22.AG13(GND277) U22.AG14(GND278) U22.AG16(GND279) U22.AG18(GND280) U22.AG20(GND281) U22.AG22(GND282) U22.AG24(GND283) U22.AG26(GND284) U22.AG28(GND285) U22.AG31(GND286) U22.AG33(GND287) U22.AG36(GND288) U22.AG39(GND289) U22.AG42(GND290) U22.AH3(GND291) U22.AH9(GND292) U22.AH12(GND293) U22.AH14(GND294) U22.AH17(GND295) U22.AH19(GND296) U22.AH21(GND297) U22.AH23(GND298) U22.AH25(GND299) U22.AH27(GND300) U22.AH29(GND301) U22.AH31(GND302) U22.AH33(GND303) U22.AH36(GND304) U22.AH39(GND305) U22.AH42(GND306) U22.AJ3(GND307) U22.AJ4(GND308) U22.AJ5(GND309) U22.AJ6(GND310) U22.AJ7(GND311) U22.AJ8(GND312) U22.AJ9(GND313) U22.AJ10(GND314) U22.AJ11(GND315) U22.AJ12(GND316) U22.AJ14(GND317) U22.AJ16(GND318) U22.AJ18(GND319) U22.AJ20(GND320) U22.AJ30(GND321) U22.AJ31(GND322) U22.AJ34(GND323) U22.AJ35(GND324) U22.AJ36(GND325) U22.AJ39(GND326) U22.AJ42(GND327) U22.AK3(GND328) U22.AK6(GND329) U22.AK9(GND330) U22.AK12(GND331) U22.AK13(GND332) U22.AK15(GND333) U22.AK17(GND334) U22.AK19(GND335) U22.AK21(S3GND01) U22.AK22(S3GND02) U22.AK23(S3GND03) U22.AK24(S3GND04) U22.AK25(S3GND05) U22.AK26(S4GND01) U22.AK27(S4GND02) U22.AK28(S4GND03) U22.AK29(S4GND04) U22.AK30(S4GND05) U22.AK33(GND336) U22.AK36(GND337) U22.AK37(GND338) U22.AK38(GND339) U22.AK39(GND340) U22.AK40(GND341) U22.AK41(GND342) U22.AK42(GND343) U22.AL3(GND344) U22.AL6(GND345) U22.AL9(GND346) U22.AL12(GND347) U22.AL20(S3GND06) U22.AL31(S4GND06) U22.AL33(GND348) U22.AL34(GND349) U22.AL39(GND350) U22.AL42(GND351) U22.AM3(GND352) U22.AM6(GND353) U22.AM9(GND354) U22.AM12(GND355) U22.AM19(S3GND07) U22.AM21(S3GND08) U22.AM22(S3GND09) U22.AM23(S3GND10) U22.AM25(S3GND11) U22.AM26(S4GND07) U22.AM28(S4GND08) U22.AM29(S4GND09) U22.AM30(S4GND10) U22.AM31(S4GND11) U22.AM32(X4GND01) U22.AM33(GND356) U22.AM36(GND357) U22.AM39(GND358) U22.AM42(GND359) U22.AN3(GND360) U22.AN6(GND361) U22.AN9(GND362) U22.AN12(GND363) U22.AN18(S3GND12) U22.AN20(X3GND01) U22.AN22(S3GND13) U22.AN24(X3GND02) U22.AN27(X4GND02) U22.AN29(S4GND12) U22.AN31(X4GND03) U22.AN34(GND364) U22.AN35(GND365) U22.AN36(GND366) U22.AN39(GND367) U22.AN42(GND368) U22.AP3(GND369) U22.AP6(GND370) U22.AP9(GND371) U22.AP12(GND372) U22.AP14(GND373) U22.AP15(GND374) U22.AP16(GND375) U22.AP18(X3GND03) U22.AP22(X3GND04) U22.AP29(X4GND04) U22.AP33(X4GND05) U22.AP37(GND376) U22.AP39(GND377) U22.AP42(GND378) U22.AR3(GND379) U22.AR6(GND380) U22.AR9(GND381) U22.AR12(GND382) U22.AR17(X3GND05) U22.AR39(GND383) U22.AR42(GND384) U22.AT3(GND385) U22.AT4(GND386) U22.AT5(GND387) U22.AT6(GND388) U22.AT7(GND389) U22.AT8(GND390) U22.AT9(GND391) U22.AT10(GND392) U22.AT11(GND393) U22.AT12(GND394) U22.AT13(GND395) U22.AT14(GND396) U22.AT15(GND397) U22.AT16(GND398) U22.AT17(X3GND06) U22.AT19(X3GND07) U22.AT21(X3GND08) U22.AT23(X3GND09) U22.AT25(X3GND10) U22.AT27(X4GND06) U22.AT29(X4GND07) U22.AT31(X4GND08) U22.AT33(X4GND09) U22.AT34(GND399) U22.AT35(GND400) U22.AT36(GND401) U22.AT39(GND402) U22.AT42(GND403) U22.AU3(GND404) U22.AU10(GND405) U22.AU17(X3GND11) U22.AU19(X3GND12) U22.AU21(X3GND13) U22.AU23(X3GND14) U22.AU25(X3GND15) U22.AU27(X4GND10) U22.AU29(X4GND11) U22.AU31(X4GND12) U22.AU33(X4GND13) U22.AU34(X4GND14) U22.AU37(GND406) U22.AU39(GND407) U22.AU41(GND408) U22.AU42(GND409) U22.AV3(GND410) U22.AV10(GND411) U22.AV17(X3GND16) U22.AV18(X3GND17) U22.AV20(X3GND18) U22.AV22(X3GND19) U22.AV24(X3GND20) U22.AV26(X4GND15) U22.AV28(X4GND16) U22.AV30(X4GND17) U22.AV32(X4GND18) U22.AV34(X4GND19) U22.AV38(GND412) U22.AV42(GND413) U22.AW3(GND414) U22.AW4(GND415) U22.AW5(GND416) U22.AW6(GND417) U22.AW7(GND418) U22.AW8(GND419) U22.AW9(GND420) U22.AW10(GND421) U22.AW11(GND422) U22.AW12(GND423) U22.AW13(GND424) U22.AW14(GND425) U22.AW15(GND426) U22.AW16(GND427) U22.AW18(X3GND21) U22.AW20(X3GND22) U22.AW22(X3GND23) U22.AW24(X3GND24) U22.AW26(X4GND20) U22.AW28(X4GND21) U22.AW30(X4GND22) U22.AW32(X4GND23) U22.AW34(X4GND24) U22.AW35(GND428) U22.AW36(GND429) U22.AW38(GND430) U22.AW40(GND431) U22.AW42(GND432) U22.AY3(GND433) U22.AY10(GND434) U22.AY17(S3GND14) U22.AY18(S3GND15) U22.AY19(S3GND16) U22.AY20(S3GND17) U22.AY21(S3GND18) U22.AY22(S3GND19) U22.AY23(S3GND20) U22.AY24(S3GND21) U22.AY25(S3GND22) U22.AY26(S4GND13) U22.AY27(S4GND14) U22.AY28(S4GND15) U22.AY29(S4GND16) U22.AY30(S4GND17) U22.AY31(S4GND18) U22.AY32(S4GND19) U22.AY33(S4GND20) U22.AY34(X4GND25) U22.AY38(GND435) U22.AY42(GND436) U22.B11(GND002) U22.B13(GND003) U22.B14(S1GND05) U22.B15(S1GND06) U22.B17(S1GND07) U22.B19(S1GND08) U22.B21(S1GND09) U22.B23(S2GND06) U22.B25(S2GND07) U22.B27(S2GND08) U22.B29(S2GND09) U22.B31(S2GND10) U22.B33(GND004) U22.B36(GND005) U22.B39(GND006) U22.B42(GND007) U22.B44(GND008) U22.BA3(GND437) U22.BA10(GND438) U22.BA17(S3GND23) U22.BA19(S3GND24) U22.BA21(S3GND25) U22.BA23(S3GND26) U22.BA25(S3GND27) U22.BA27(S4GND21) U22.BA29(S4GND22) U22.BA31(S4GND23) U22.BA33(S4GND24) U22.BA34(GND439) U22.BA38(GND440) U22.BA42(GND441) U22.BB3(GND_DET2) U22.BB4(GND442) U22.BB5(GND443) U22.BB6(GND444) U22.BB7(GND445) U22.BB8(GND446) U22.BB9(GND447) U22.BB10(GND448) U22.BB11(GND449) U22.BB12(GND450) U22.BB13(GND451) U22.BB14(GND452) U22.BB15(GND453) U22.BB16(GND454) U22.BB17(S3GND28) U22.BB19(S3GND29) U22.BB21(S3GND30) U22.BB23(S3GND31) U22.BB25(S3GND32) U22.BB27(S4GND25) U22.BB29(S4GND26) U22.BB31(S4GND27) U22.BB33(S4GND28) U22.BB34(S4GND29) U22.BB35(GND455) U22.BB36(GND456) U22.BB37(GND457) U22.BB38(GND458) U22.BB39(GND459) U22.BB40(GND460) U22.BB41(GND461) U22.BB42(GND_DET3) U22.BC17(S3GND33) U22.BC18(S3GND34) U22.BC20(S3GND35) U22.BC22(S3GND36) U22.BC24(S3GND37) U22.BC26(S4GND30) U22.BC28(S4GND31) U22.BC30(S4GND32) U22.BC32(S4GND33) U22.BC34(S4GND34) U22.BD18(S3GND38) U22.BD20(S3GND39) U22.BD22(S3GND40) U22.BD24(S3GND41) U22.BD26(S4GND35) U22.BD28(S4GND36) U22.BD30(S4GND37) U22.BD32(S4GND38) U22.BD34(S4GND39) U22.C3(GND_DET1) U22.C4(GND009) U22.C5(GND010) U22.C6(GND011) U22.C7(GND012) U22.C8(GND013) U22.C9(GND014) U22.C14(S1GND10) U22.C16(S1GND11) U22.C18(S1GND12) U22.C20(S1GND13) U22.C22(S1GND14) U22.C24(S2GND11) U22.C26(S2GND12) U22.C28(S2GND13) U22.C30(S2GND14) U22.C31(S2GND15) U22.D3(GND015) U22.D9(GND016) U22.D14(S1GND15) U22.D16(S1GND16) U22.D18(S1GND17) U22.D20(S1GND18) U22.D22(S1GND19) U22.D24(S2GND16) U22.D26(S2GND17) U22.D28(S2GND18) U22.D30(S2GND19) U22.D32(USB_AGND1) U22.D34(GND017) U22.D37(GND018) U22.D40(GND019) U22.D43(GND020) U22.E3(GND021) U22.E6(GND022) U22.E9(GND023) U22.E11(GND024) U22.E14(S1GND20) U22.E15(S1GND21) U22.E16(S1GND22) U22.E17(S1GND23) U22.E18(S1GND24) U22.E19(S1GND25) U22.E20(S1GND26) U22.E21(S1GND27) U22.E22(S1GND28) U22.E23(S2GND20) U22.E24(S2GND21) U22.E25(S2GND22) U22.E26(S2GND23) U22.E27(S2GND24) U22.E28(S2GND25) U22.E29(S2GND26) U22.E30(S2GND27) U22.E31(X2GND01) U22.F3(GND025) U22.F4(GND026) U22.F8(GND027) U22.F9(GND028) U22.F13(GND029) U22.F15(X1GND01) U22.F17(X1GND02) U22.F19(X1GND03) U22.F21(X1GND04) U22.F23(X2GND02) U22.F25(X2GND03) U22.F27(X2GND04) U22.F29(X2GND05) U22.F31(X2GND06) U22.F33(GND030) U22.F36(GND031) U22.F39(GND032) U22.F41(GND033) U22.G3(GND034) U22.G6(GND035) U22.G9(GND036) U22.G14(X1GND05) U22.G15(X1GND06) U22.G17(X1GND07) U22.G19(X1GND08) U22.G21(X1GND09) U22.G23(X2GND07) U22.G25(X2GND08) U22.G27(X2GND09) U22.G29(X2GND10) U22.G31(X2GND11) U22.G43(GND037) U22.H3(GND038) U22.H9(GND039) U22.H11(GND040) U22.H14(X1GND10) U22.H16(X1GND11) U22.H18(X1GND12) U22.H20(X1GND13) U22.H22(X1GND14) U22.H24(X2GND12) U22.H26(X2GND13) U22.H28(X2GND14) U22.H30(X2GND15) U22.H31(X2GND16) U22.H34(GND041) U22.H37(GND042) U22.H39(GND043) U22.J3(GND044) U22.J5(GND045) U22.J7(GND046) U22.J9(GND047) U22.J13(GND048) U22.J14(X1GND15) U22.J16(X1GND16) U22.J18(X1GND17) U22.J20(X1GND18) U22.J22(X1GND19) U22.J24(X2GND17) U22.J26(X2GND18) U22.J28(X2GND19) U22.J30(X2GND20) U22.J32(USB_AGND2) U22.J41(GND049) U22.J44(GND050) U22.K3(GND051) U22.K6(GND052) U22.K9(GND053) U22.K14(X1GND20) U22.K33(GND054) U22.K36(GND055) U22.K43(GND056) U22.L3(GND057) U22.L6(GND058) U22.L9(GND059) U22.L11(GND060) U22.L15(X1GND21) U22.L19(X1GND22) U22.L26(X2GND21) U22.L30(X2GND22) U22.L31(USB_AGND3) U22.L39(GND061) U22.M3(GND062) U22.M6(GND063) U22.M9(GND064) U22.M13(GND065) U22.M15(S1GND29) U22.M17(X1GND23) U22.M19(S1GND30) U22.M21(X1GND24) U22.M24(X2GND23) U22.M26(S2GND28) U22.M28(X2GND24) U22.M32(USB_AGND4) U22.M34(GND066) U22.M41(GND067) U22.M44(GND068) U22.N3(GND069) U22.N6(GND070) U22.N9(GND071) U22.N16(S1GND31) U22.N18(S1GND32) U22.N19(S1GND33) U22.N20(S1GND34) U22.N22(S1GND35) U22.N23(S2GND29) U22.N25(S2GND30) U22.N26(S2GND31) U22.N27(S2GND32) U22.N28(S2GND33) U22.N29(X2GND25) U22.N30(USB_AGND5) U22.N37(GND072) U22.N43(GND073) U22.P3(GND074) U22.P6(GND075) U22.P9(GND076) U22.P11(GND077) U22.P14(GND078) U22.P15(GND079) U22.P16(GND080) U22.P17(S1GND36) U22.P28(S2GND34) U22.P33(GND081) U22.P39(GND082) U22.R3(GND083) U22.R6(GND084) U22.R9(GND085) U22.R18(S1GND37) U22.R19(S1GND38) U22.R20(S1GND39) U22.R21(S1GND40) U22.R22(S1GND41) U22.R23(S2GND35) U22.R24(S2GND36) U22.R25(S2GND37) U22.R26(S2GND38) U22.R27(S2GND39) U22.R31(GND086) U22.R41(GND087) U22.T3(GND088) U22.T6(GND089) U22.T9(GND090) U22.T10(GND091) U22.T11(GND092) U22.T12(GND093) U22.T14(GND094) U22.T17(GND095) U22.T31(GND096) U22.T37(GND097) U22.T43(GND098) U22.U3(GND099) U22.U6(GND100) U22.U13(GND101) U22.U14(GND102) U22.U16(GND103) U22.U18(GND104) U22.U20(GND105) U22.U22(GND106) U22.U24(GND107) U22.U26(GND108) U22.U28(GND109) U22.U31(GND110) U22.U33(GND111) U22.U39(GND112) U22.V3(GND113) U22.V6(GND114) U22.V9(GND115) U22.V12(GND116) U22.V14(GND117) U22.V17(GND118) U22.V19(GND119) U22.V21(GND120) U22.V23(GND121) U22.V25(GND122) U22.V27(GND123) U22.V29(GND124) U22.V31(GND125) U22.V34(GND126) U22.V41(GND127) U22.W3(GND128) U22.W6(GND129) U22.W9(GND130) U22.W12(GND131) U22.W13(GND132) U22.W14(GND133) U22.W16(GND134) U22.W18(GND135) U22.W20(GND136) U22.W22(GND137) U22.W24(GND138) U22.W26(GND139) U22.W28(GND140) U22.W31(GND141) U22.W33(GND142) U22.W37(GND143) U22.W43(GND144) U22.Y3(GND145) U22.Y6(GND146) U22.Y9(GND147) U22.Y14(GND148) U22.Y17(GND149) U22.Y19(GND150) U22.Y21(GND151) U22.Y23(GND152) U22.Y25(GND153) U22.Y27(GND154) U22.Y29(GND155) U22.Y31(GND156) U22.Y35(GND157) U22.Y36(GND158) U22.Y37(GND159) U22.Y38(GND160) U22.Y39(GND161) U22.Y40(GND162) U22.Y41(GND163) U22.Y42(GND164) U32.7(OEB_OUT1:0) U32.8(OEB_OUT2) U32.11(GND_1) U32.12(GND_2) U32.20(OEB_OUT3) U32.31(OEB_OUT4) U32.32(OEB_OUT5) U32.36(OEB_OUT6) U32.41(GND_EPAD) U36.65(GND_PAD) U626.1(GND) U626.9(GND_2) U626.17(EPAD) U627.1(GND) U627.9(GND_2) U627.17(EPAD) ; also on sheet 6 7 8 9 10 11 12 13 14 15 16 18 19 20 21 28 29 30 31 32 33 34 35 36 37 38 39 40 41 42 43 44 45 46 47 48 49 50 51 52 53 54
VCC_3.3: C3865.1 C5328.1 C5329.1 FB23.1 FB87.1 FL18.3(OUT_IN) FL20.1(IN_OUT) R5704.1 R5705.1 R5706.1 U626.4(VDD) U627.4(VDD) ; also on sheet 6 12 13 16 18 31 32 33 36 39 40 41 42 43 44 47 48 49 50 51 53
VCC_DVDD: R720.1 R726.1 ; also on sheet 20 50 52
VDD_LP: R717.2 ; also on sheet 20
ASLEEP: R762.2 R5762.1 U22.G34(ASLEEP) ; also on sheet 8
CFG_DDRCLK: U627.8(CLK_SEL) ; also on sheet 8
CFG_SYSCLK: U626.8(CLK_SEL) ; also on sheet 8
CFG_TESTSEL_B: R765.2 U22.F34(~{TEST_SEL}) ; also on sheet 8
CKGEN_VDDO0: C3853.1 FL13.1(IN_OUT) U36.22(VDDO0)
CKGEN_VDDO1: C3855.1 FL16.1(IN_OUT) U36.26(VDDO1)
CKGEN_VDDO2: C3863.1 FL18.1(IN_OUT) U36.29(VDDO2)
CKGEN_VDDO3: C3867.1 FL21.1(IN_OUT) U36.33(VDDO3)
CKGEN_VDDO4: C3869.1 FL23.1(IN_OUT) U36.36(VDDO4)
CKGEN_VDDO5: C3854.1 FL14.1(IN_OUT) U36.40(VDDO5)
CKGEN_VDDO6: C3856.1 FL17.1(IN_OUT) U36.43(VDDO6)
CKGEN_VDDO7: C3864.1 FL19.1(IN_OUT) U36.49(VDDO7)
CKGEN_VDDO8: C3868.1 FL22.1(IN_OUT) U36.52(VDDO8)
CKGEN_VDDO9: C3870.1 FL24.1(IN_OUT) U36.57(VDDO9)
CKSTPO_B: J2.15(A8) R67.1 TP213.1(TP) U22.L44(~{CKSTP_OUT})
CLK_ENET1: R5849.2 ; also on sheet 42
CLK_ENET2: R5850.2 ; also on sheet 43
CLK_PCIE_REF_N: C3874.2 U32.3(CLK_IN1B)
CLK_PCIE_REF_P: C3873.2 U32.2(CLK_IN1)
CLK_RETIMER: C5310.2 ; also on sheet 38
CLK_SE1_100MHZ: R5708.2 U626.7(CLK1)
CLK_SE2_100MHZ: R5726.2 U627.7(CLK1)
CLK_SE_66MHZ: R5707.2 U626.5(CLK0)
CLK_SE_133MHZ: R5724.2 U627.5(CLK0)
CLK_USB: R5713.2 ; also on sheet 49
CLKU0_P: R5707.1 U36.24(OUT0)
CLKU1_N: C3882.1 U36.27(~{OUT1})
CLKU1_P: C3881.1 U36.28(OUT1)
CLKU2_N: R5850.1 U36.30(~{OUT2})
CLKU2_P: R5849.1 U36.31(OUT2)
CLKU3_P: R5722.1 U36.35(OUT3)
CLKU4_N: C3874.1 U36.37(~{OUT4})
CLKU4_P: C3873.1 U36.38(OUT4)
CLKU5_N: C5311.1 U36.41(~{OUT5})
CLKU5_P: C5310.1 U36.42(OUT5)
CLKU6_N: R5726.1 U36.44(~{OUT6})
CLKU6_P: R5708.1 U36.45(OUT6)
CLKU7_N: R5848.1 U36.50(~{OUT7})
CLKU7_P: R5847.1 U36.51(OUT7)
CLKU8_P: R5713.1 U36.54(OUT8)
CLKU9_P: R5724.1 U36.59(OUT9)
COP_HRST_B: J2.13(A7) R68.1 ; also on sheet 8
COP_SRST_B: J2.11(A6) R69.1 ; also on sheet 8
COP_TCK: J2.7(A4) R71.1 U22.K44(TCK)
COP_TDI: J2.3(A2) R74.1 U22.J43(TDI)
COP_TDO: J2.1(A1) U22.K42(TDO)
COP_TMS: J2.9(A5) R70.1 U22.K41(TMS)
COP_TRST_B: J2.4(B2) R73.1 ; also on sheet 8
COP_VDD_SNS: J2.6(B3) R72.2
DDRCLK: R698.1 R5896.2
DUT_DMA0: R268.1 U22.P43(~{DMA1_DREQ0})
DUT_DMA1: TP2.1(TP) U22.R43(~{DMA1_DACK0})
DUT_DMA2: TP1.1(TP) U22.R44(~{DMA1_DDONE0})
DUT_DMA3: R732.1 U22.N41(~{DMA2_DREQ0})
DUT_DMA4: TP4.1(TP) U22.P44(~{DMA2_DACK0})
DUT_DMA5: TP3.1(TP) U22.P42(~{DMA2_DDONE0})
DUT_HRESET_B: R767.2 U22.D35(~{HRESET}) ; also on sheet 8
DUT_PORESET_B: R766.2 U22.F35(~{PORESET}) ; also on sheet 8
DUT_RESET_REQ_B: R763.2 U22.G33(~{RESET_REQ}) ; also on sheet 8
DUT_TRST_B: U22.J42(~{TRST}) ; also on sheet 8
DUT_UART1_CTS_B: U22.N11(~{UART1_CTS}) ; also on sheet 52
DUT_UART1_RTS_B: U22.M10(~{UART1_RTS}) ; also on sheet 52
DUT_UART1_RXD: U22.M11(UART1_SIN) ; also on sheet 52
DUT_UART1_TXD: U22.L10(UART1_SOUT) ; also on sheet 52
DUT_UART2_CTS_B: U22.K11(~{UART2_CTS}) ; also on sheet 52
DUT_UART2_RTS_B: U22.K10(~{UART2_RTS}) ; also on sheet 52
DUT_UART2_RXD: U22.J11(UART2_SIN) ; also on sheet 52
DUT_UART2_TXD: U22.J10(UART2_SOUT) ; also on sheet 52
EC1_GTX_CLK125: R5847.2 ; also on sheet 45
EC2_GTX_CLK125: R5848.2 ; also on sheet 45
EVT0_B: R5853.2 TP86.1(TP) U22.N42(~{EVT0})
EVT1_B: R5854.2 TP6.1(TP) U22.M43(~{EVT1})
EVT2_B: R5855.2 TP7.1(TP) U22.M42(~{EVT2})
EVT3_B: R5856.2 TP9.1(TP) U22.L43(~{EVT3})
EVT4_B: R5857.2 TP8.1(TP) U22.L42(~{EVT4})
FA_ANALOG_G_V: R718.1 U22.R32(FA_ANALOG_G_V)
FA_ANALOG_PIN: R715.1 U22.T32(FA_ANALOG_PIN)
I2C1_PROC_SCL: U22.R10(IIC1_SCL) ; also on sheet 50
I2C1_PROC_SDA: U22.R11(IIC1_SDA) ; also on sheet 50
I2C1_SCL: U36.16(SCLK) ; also on sheet 8 12 31 32 33 50 51 53
I2C1_SDA: U36.18(SDA/SDIO) ; also on sheet 8 12 31 32 33 50 51 53
I2C2_PROC_SCL: U22.N10(IIC2_SCL) ; also on sheet 50
I2C2_PROC_SDA: U22.P10(IIC2_SDA) ; also on sheet 50
I2C4_SCL: R726.2 U22.N12(IIC4_SCL)
I2C4_SDA: R720.2 U22.P12(IIC4_SDA)
INJ_DDRCLK: R698.2 U22.AL14(DDRCLK)
INJ_SYSCLK: R711.2 U22.U34(SYSCLK)
IRQ0_B: R254.2 U22.V43(IRQ00) ; also on sheet 8
IRQ1_B: R253.2 U22.V44(IRQ01) ; also on sheet 8
IRQ2_B: R257.2 U22.U43(IRQ02) ; also on sheet 8
IRQ3_B: R251.2 U22.W42(IRQ03) ; also on sheet 8
IRQ4_B: R258.2 U22.U44(IRQ04) ; also on sheet 8
IRQ5_B: R266.2 U22.R42(IRQ05) ; also on sheet 8
IRQ6_B: R252.2 U22.W41(IRQ06) ; also on sheet 8
IRQ7_B: R263.2 U22.T42(IRQ07) ; also on sheet 8
IRQ8_B: R262.2 U22.T44(IRQ08) ; also on sheet 8
IRQ9_B: R255.2 U22.V42(IRQ09) ; also on sheet 8
IRQ10_B: R250.2 U22.W44(IRQ10) ; also on sheet 8
IRQ11_B: R260.2 U22.U42(IRQ11) ; also on sheet 8
IRQ_CLOCK_B: U36.12(~{INTR}) ; also on sheet 8
IRQ_OUT_B: R265.2 U22.T41(~{IRQ_OUT})
LP_TMP_DETECT_B: R717.1 TP206.1(TP) U22.T27(~{LP_TMP_DETECT})
MON_DDRCLK: U627.10(Q7) ; also on sheet 8
MON_SYSCLK: U626.10(Q7) ; also on sheet 8
ORIENT_ERR_B: U22.C42(NC_DET) ; also on sheet 8
OVDD: C3857.1 C3858.1 C5327.1 C5330.1 FB1.1 FL13.3(OUT_IN) FL15.1(IN_OUT) FL16.3(OUT_IN) FL17.3(OUT_IN) FL21.3(OUT_IN) FL22.3(OUT_IN) FL23.3(OUT_IN) FL24.3(OUT_IN) R250.1 R251.1 R252.1 R253.1 R254.1 R255.1 R257.1 R258.1 R260.1 R262.1 R263.1 R265.1 R266.1 R268.2 R732.2 R762.1 R763.1 R764.1 R765.1 R766.1 R767.1 R768.1 R5853.1 R5854.1 R5855.1 R5856.1 R5857.1 U626.12(VDDO) U627.12(VDDO) ; also on sheet 10 11 18 20 21 34 35 36
PCIE_REFCLK_N: U32.34(OUT6B) ; also on sheet 48
PCIE_REFCLK_P: U32.35(OUT6) ; also on sheet 48
PCIE_X4_CLK_N: U32.29(OUT5B) ; also on sheet 47
PCIE_X4_CLK_P: U32.30(OUT5) ; also on sheet 47
PEXBUFCOREV: C309.1 C310.1 C332.1 C334.1 FB23.2 U32.1(VDD_DIG) U32.4(VDD) U32.9(VDDA) U32.37(OEB_OUT7)
PEXBUFIOV: C3889.1 C3890.1 C3891.1 C3892.1 FB87.2 U32.15(VDDO0) U32.18(VDDO1) U32.25(VDDO2) U32.28(VDDO3) U32.33(VDDO4) U32.40(VDDO5)
RST_CLKGEN_B: U36.6(~{RST}) ; also on sheet 8
RTCCLK_DUT: R5722.2 U22.V33(RTC)
SCANMODE: R764.2 U22.E33(~{SCAN_MODE})
SD1_REFCLK1_N: U32.13(OUT0B) ; also on sheet 37
SD1_REFCLK1_P: U32.14(OUT0) ; also on sheet 37
SD2_REFCLK1_N: C3882.2 ; also on sheet 37
SD2_REFCLK1_P: C3881.2 ; also on sheet 37
SD2_REFCLK2_N: U32.16(OUT1B) ; also on sheet 37
SD2_REFCLK2_P: U32.17(OUT1) ; also on sheet 37
SD3_REFCLK1_N: U32.21(OUT2B) ; also on sheet 46
SD3_REFCLK1_P: U32.22(OUT2) ; also on sheet 46
SD4_REFCLK1_N: U32.23(OUT3B) ; also on sheet 46
SD4_REFCLK1_P: U32.24(OUT3) ; also on sheet 46
SD4_REFCLK2_N: U32.26(OUT4B) ; also on sheet 46
SD4_REFCLK2_P: U32.27(OUT4) ; also on sheet 46
SDHC_CD_B: U22.N13(IIC3_SCL) ; also on sheet 36
SDHC_WP: U22.P13(IIC3_SDA) ; also on sheet 36
SI5341_A0CS: R5711.1 U36.19(A0/~{CS})
SI5341_A1SDO: R5710.1 U36.17(A1/SDO)
SI5341_FDEC: TP209.1(TP) U36.25(FDEC)
SI5341_FINC: TP208.1(TP) U36.48(FINC)
SI5341_I2CSEL: R5704.2 U36.39(I2C_SEL)
SI5341_INSEL0: R5706.2 U36.3(IN_SEL0)
SI5341_INSEL1: R5705.2 U36.4(IN_SEL1)
SI5341_LOL_B: TP214.1(TP) U36.47(~{LOL})
SI5341_OE_B: R5712.1 U36.11(~{OE})
SI5341_SYNC_B: TP210.1(TP) U36.5(~{SYNC})
SI5341_VDD: C3859.1 C3860.1 C3861.1 C3862.1 FL15.3(OUT_IN) U36.32(VDD1) U36.46(VDD2) U36.60(VDD3)
SI5341_VDDA: C3866.1 FL20.3(OUT_IN) U36.13(VDDA)
SYSCLK: R711.1 R5895.2
TEMP_DIODE1_N: U22.Y34(TD1_CATHODE) ; also on sheet 51
TEMP_DIODE1_P: U22.AA34(TD1_ANODE) ; also on sheet 51
TEMP_DIODE2_N: U22.AL17(TD2_CATHODE) ; also on sheet 51
TEMP_DIODE2_P: U22.AL16(TD2_ANODE) ; also on sheet 51
TH_TPA: TP84.1(TP) U22.W32(TH_TPA)
UTCKO: TP5.1(TP) U22.N44(CLK_OUT)
X1_GND: U36.7(X1) U36.10(X2) Y7.2 Y7.4
XA_SI5341B: U36.8(XA) Y7.1
XB_SI5341B: U36.9(XB) Y7.3
Z5402: FB1.2 R67.2 R68.2 R69.2 R70.2 R71.2 R72.1 R73.2 R74.2
N16862198: R768.2 TP205.1(TP) U22.E35(~{TMP_DETECT})
N31081508: TP212.1(TP) U32.10(LOS)
N31116021: R5721.1 U32.19(IMP_SEL)
N34216244: R5895.1 U626.16(Q2)
N34216367: TP287.1(TP) U626.6(OE)
N34216393: TP288.1(TP) U627.6(OE)
N34216534: R5896.1 U627.16(Q2)

Not connected (* = marked no-connect by the designer): C5311 2*; J2 2(B1)* 5(A3)* 8(B4)* 10(B5)* 14(B7)*; U22 AE32(NC64)* AG32(NC65)* AH32(NC66)* AJ32(NC67)* AJ33(NC68)* AK31(NC69)* AK32(NC70)* AL15(NC71)* AL18(NC72)* AL19(NC73)* AL32(NC74)* AM14(NC75)* AM15(NC76)* AM18(NC77)* AN13(NC78)* AN14(NC79)* AN15(NC80)* AN16(NC81)* AN17(NC82)* AP17(NC83)* AW17(NC84)* G35(NC01)* G36(NC02)* G37(NC03)* G38(NC04)* H33(NC05)* H35(NC06)* H36(NC07)* H38(NC08)* J33(NC09)* J34(NC10)* J35(NC11)* J36(NC12)* J37(NC13)* J38(NC14)* K34(NC15)* K35(NC16)* K37(NC17)* K38(NC18)* L33(NC19)* L34(NC20)* L35(NC21)* L36(NC22)* L37(NC23)* L38(NC24)* M33(NC25)* M35(NC26)* M36(NC27)* M37(NC28)* M38(NC29)* N33(NC30)* N34(NC31)* N35(NC32)* N36(NC33)* N38(NC34)* P34(NC35)* P35(NC36)* P36(NC37)* P37(NC38)* P38(NC39)* R34(NC40)* R35(NC41)* R36(NC42)* R37(NC43)* R38(NC44)* T18(NC45)* T33(NC46)* T34(NC47)* T35(NC48)* T36(NC49)* T38(NC50)* U32(NC51)* U35(NC52)* U36(NC53)* U37(NC54)* U38(NC55)* V35(NC56)* V36(NC57)* V37(NC58)* V38(NC59)* W34(NC60)* W35(NC61)* W36(NC62)* W38(NC63)*; U32 5(NC_1)* 6(NC_2)* 38(OUT7B)* 39(OUT7)*; U36 1(IN1)* 2(~{IN1})* 14(IN2)* 15(~{IN2})* 20(RSVD1)* 21(RSVD2)* 23(~{OUT0})* 34(~{OUT3})* 53(~{OUT8})* 55(RSVD3)* 56(RSVD4)* 58(~{OUT9})* 61(FB_IN)* 62(~{FB_IN})* 63(IN0)* 64(~{IN0})*; U626 2(Q1)* 3(Q0)* 11(Q6)* 13(Q5)* 14(Q4)* 15(Q3)*; U627 2(Q1)* 3(Q0)* 11(Q6)* 13(Q5)* 14(Q4)* 15(Q3)*

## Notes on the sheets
sheet 22
- T4240 Ground Pins
sheet 23
- T4240 NC Pins
- NOTE: NC_DET pin is normally NC and floating.
        If the device is mis-installed in any other rotation,
        a GND pad will be at the C42 pin location and the
        ORIENT_ERR_B signal will be asserted low.
sheet 24
- SYSCLK / DDRCLK / REF Clocks
- OUT0: 66.6666 MHz
               LVCMOS 1.8V
               to T4240 SYSCLK (default)
- Crystal guard ring
  ==============================
  Route X1_GND net around crystal
  and behind Si5341 pins for full
  enclosing circle.
- OUT1: 156.25 MHz
               HCSL 1.8V
               to T4240 SD2_REF1
- OUT2: 125.00000 MHz
               LVCMOS 3.3V
               to 1G PHYs
- Crystal Load Caps
  =========================
  Si5341B features internal
  crystal trimming.
- OUT3: 3.125 MHz
               LVCMOS 1.8V
               to T4240 RTC_CLK
- OUT4: 100.00000 MHz
               HCSL 1.8V
               to PCIe CLK BUF
- OUT5:  25.0000 MHz
               LVCMOS 2.5V
               to XFI RETIMER
- OUT6: 100.0000 MHz
               LVCMOS 1.8V
               to T4240 SYSCLK / DDRCLK
- OUT7: 125.00000 MHz
               LVCMOS 2.5V
               to T4240 ENET
- OUT8: 24.0000 MHz
               LVCMOS 1.8V
               to T4240 USB_CLK
- OUT9: 133.3333 MHz
               LVCMOS 1.8V
               to T4240 DDR_CLK (default)
- I2C ADDRESS
  0x74
sheet 25
- PCIe Clock Buffers
- IMP_SEL=0
  Z=100 ohm
- DUT Clock Select
- (int p/u)
- (int p/u)
sheet 27
- T4240 System Block & COP
- cfg_xvdd_sel - ASLEEP
  ------------------------
  >1= 1.35V ONLY
- OVDD
- ----------------DVDD----------------
- ----------------DVDD----------------
- ---------------OVDD--------------
- OPTION
  Remove resistors to inject
  arbitrary SYSCLK/DDRCLK
  frequencies.
